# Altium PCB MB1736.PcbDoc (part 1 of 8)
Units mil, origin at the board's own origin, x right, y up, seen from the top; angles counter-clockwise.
Board outline 5905.51 x 3779.53 mil, 6 copper layers (Top Layer, L2_GND, L3_SIG, L4_VCC, L5_GND, Bottom Layer), stack 117.811 mil thick; 481 components, 387 nets, 1904 pads, 1200 vias.
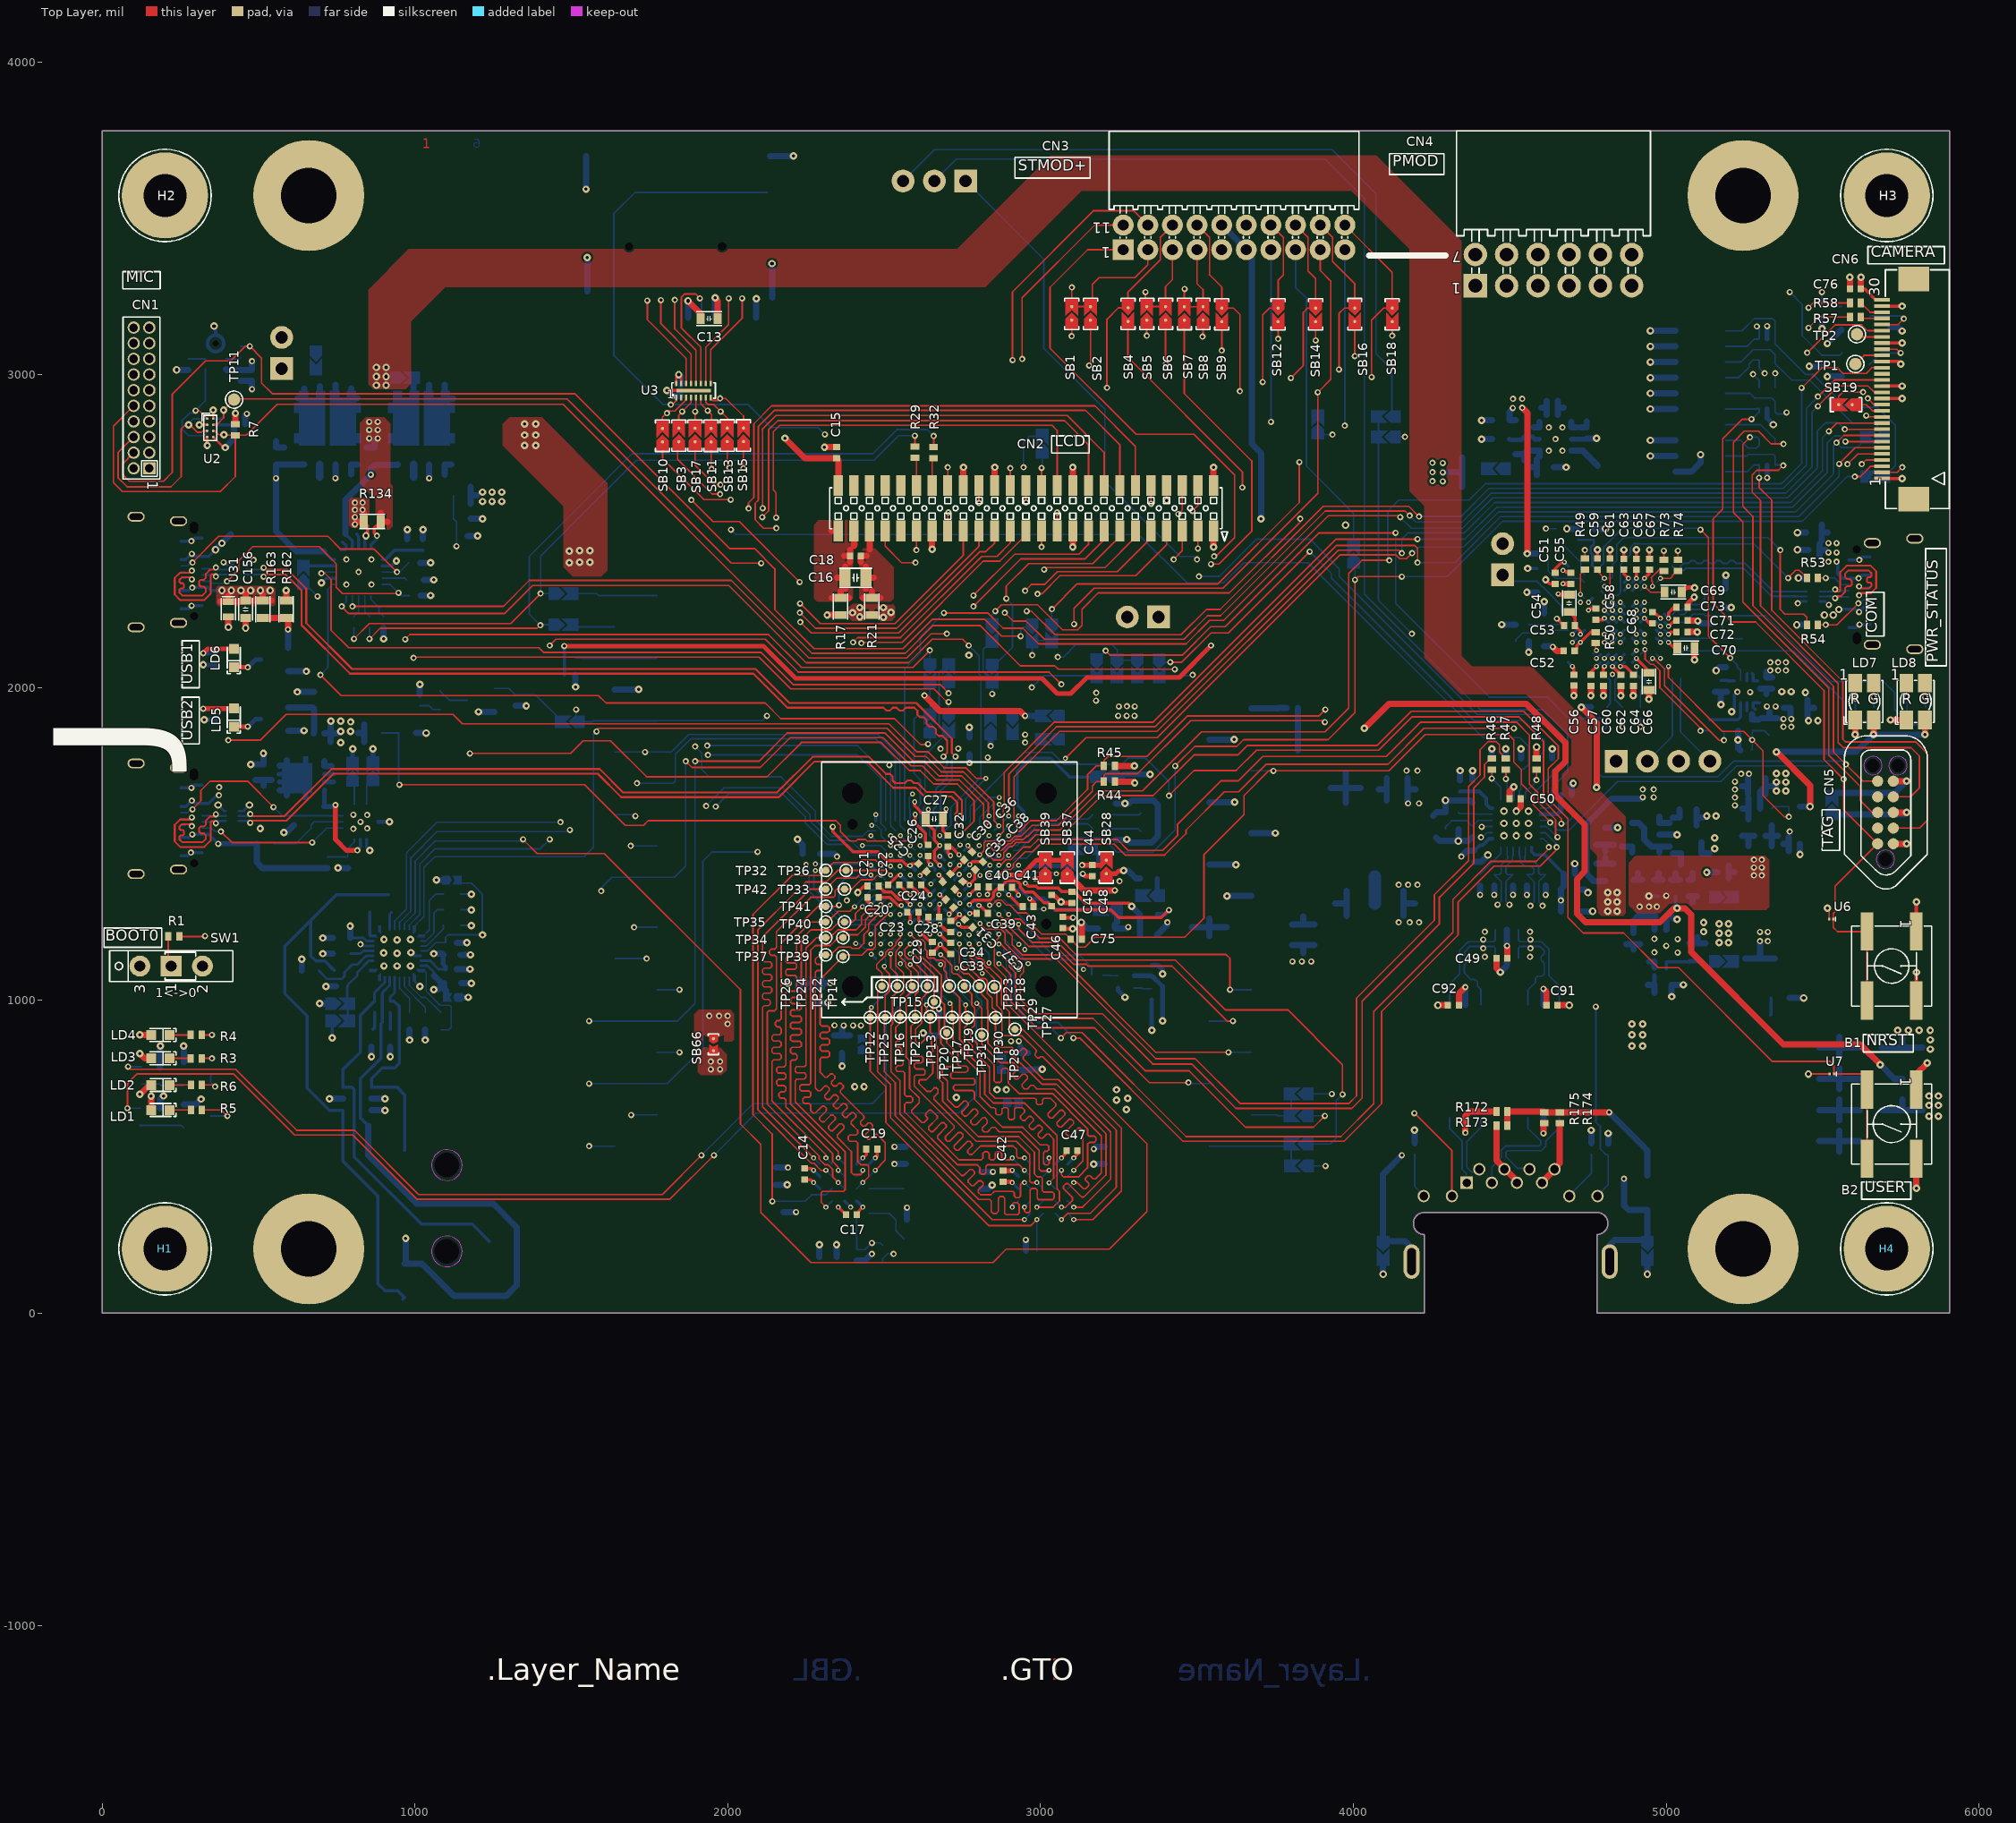
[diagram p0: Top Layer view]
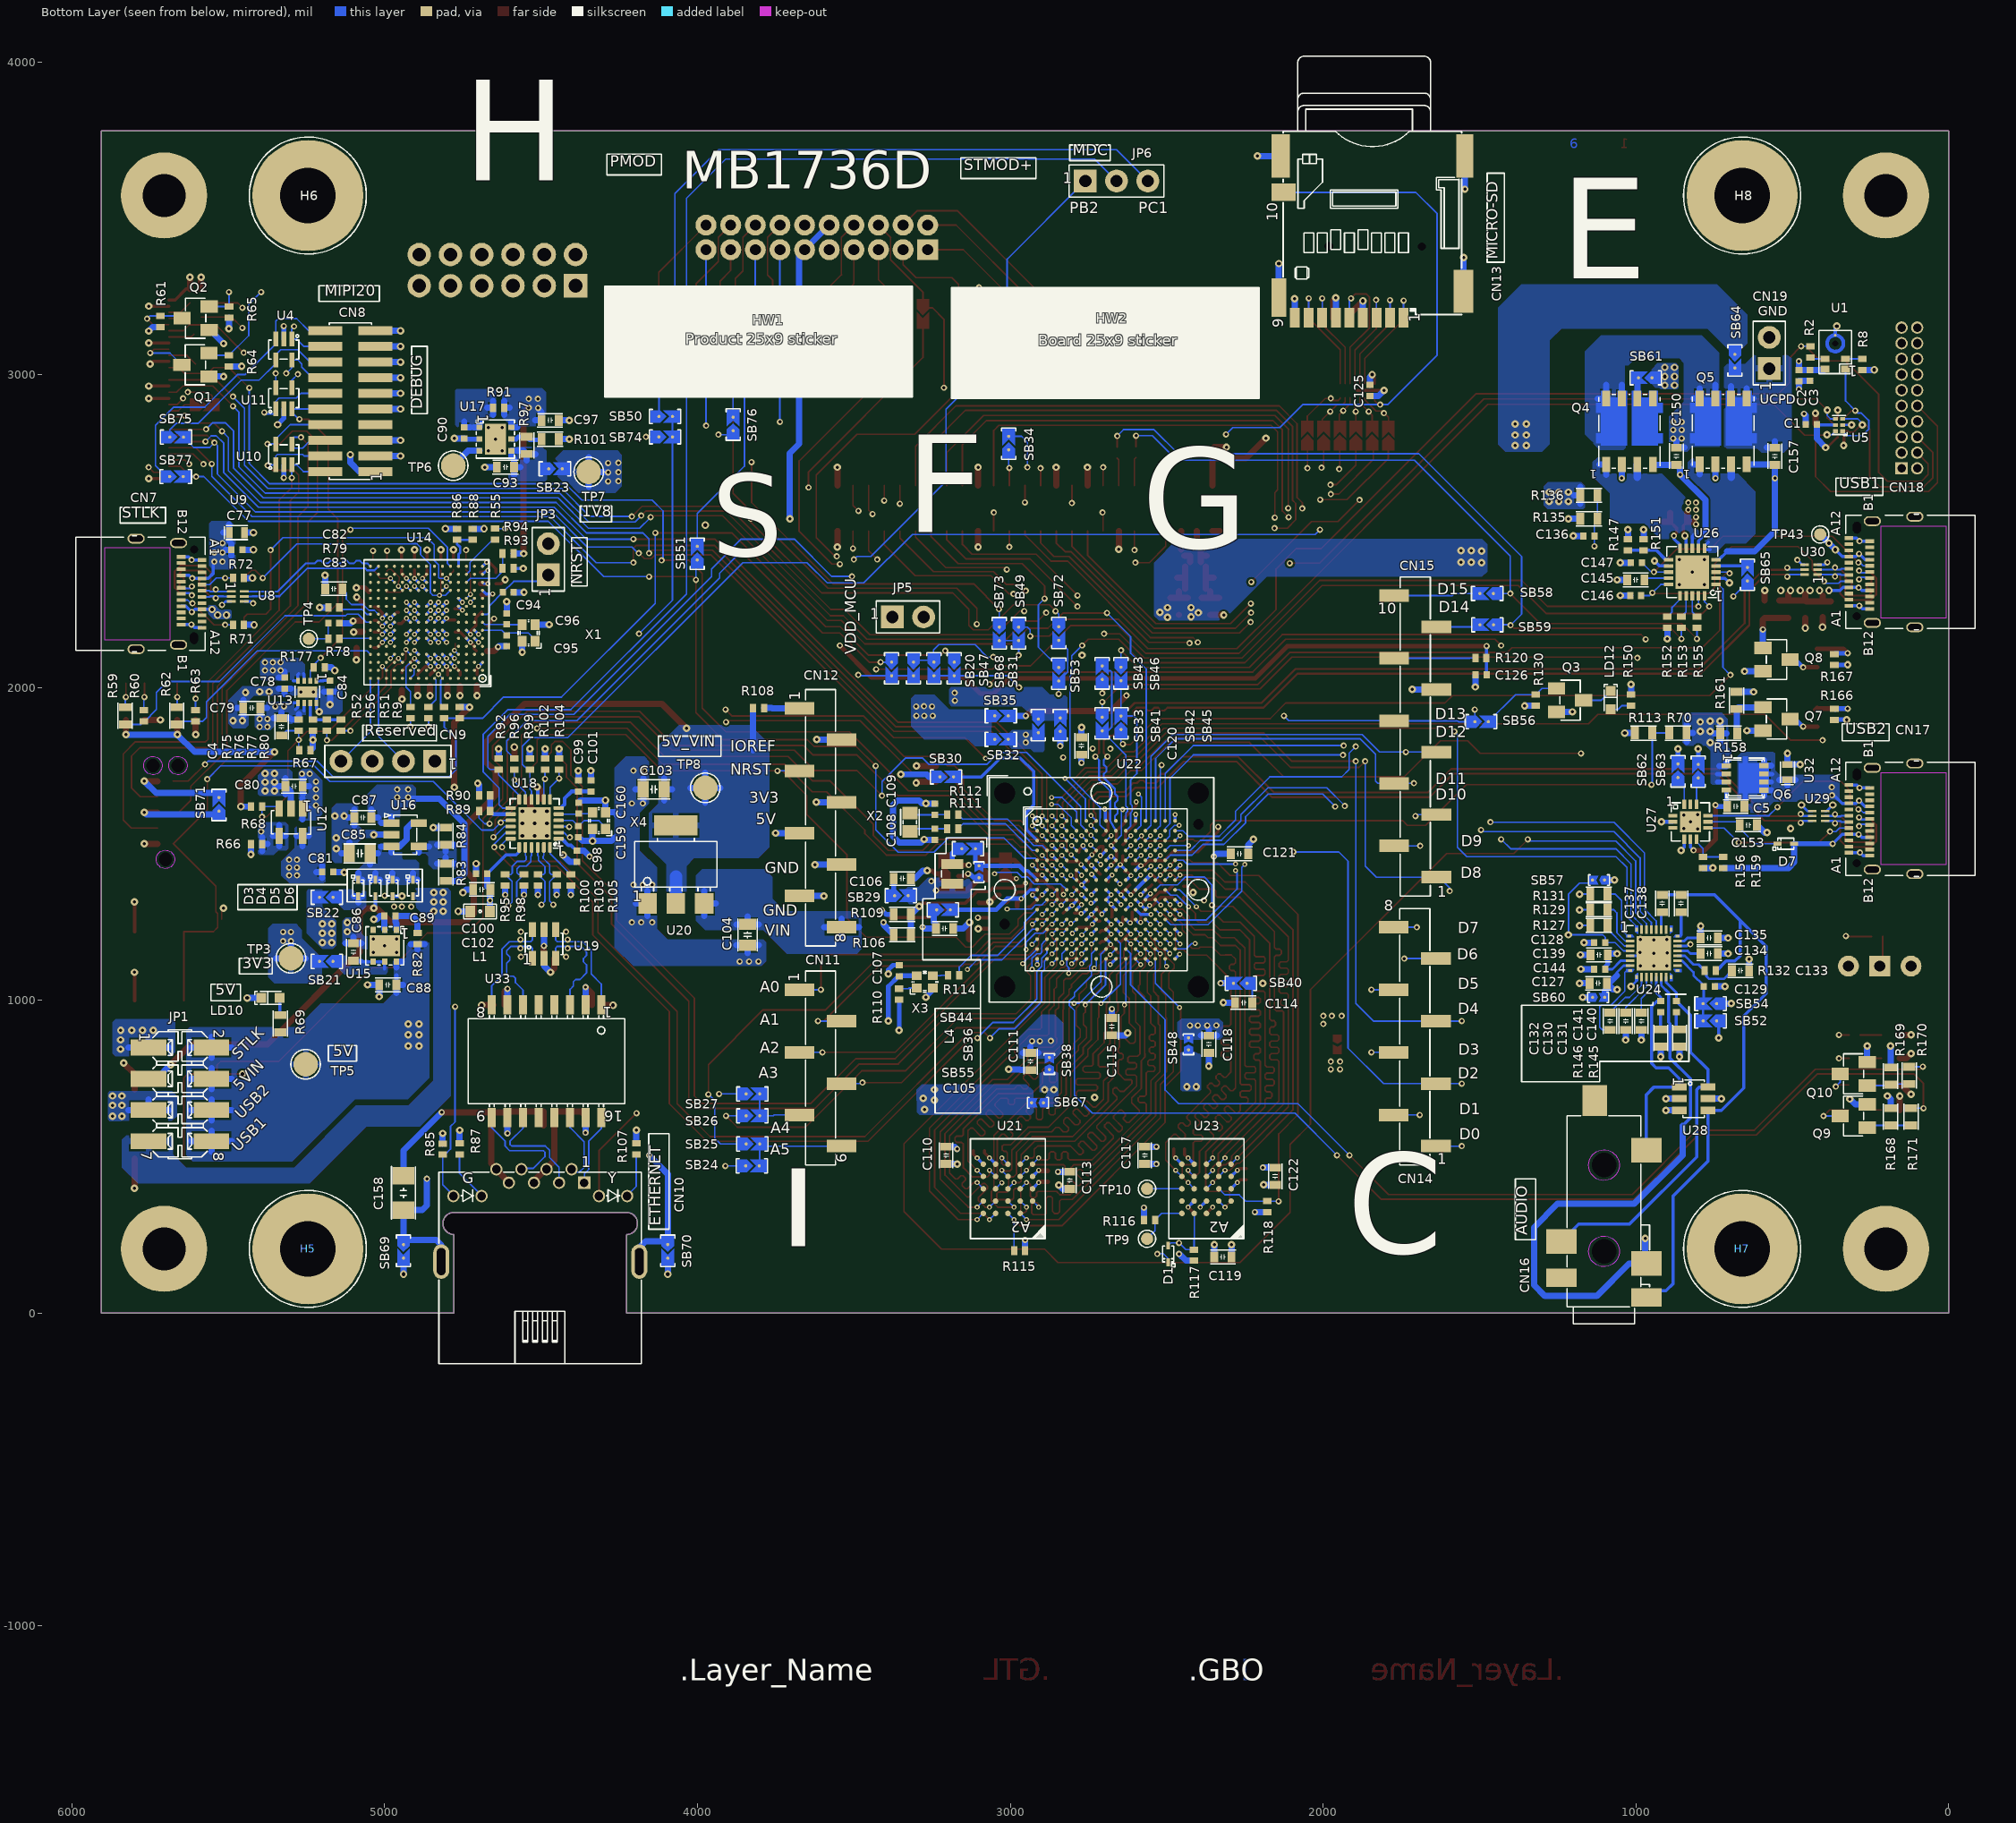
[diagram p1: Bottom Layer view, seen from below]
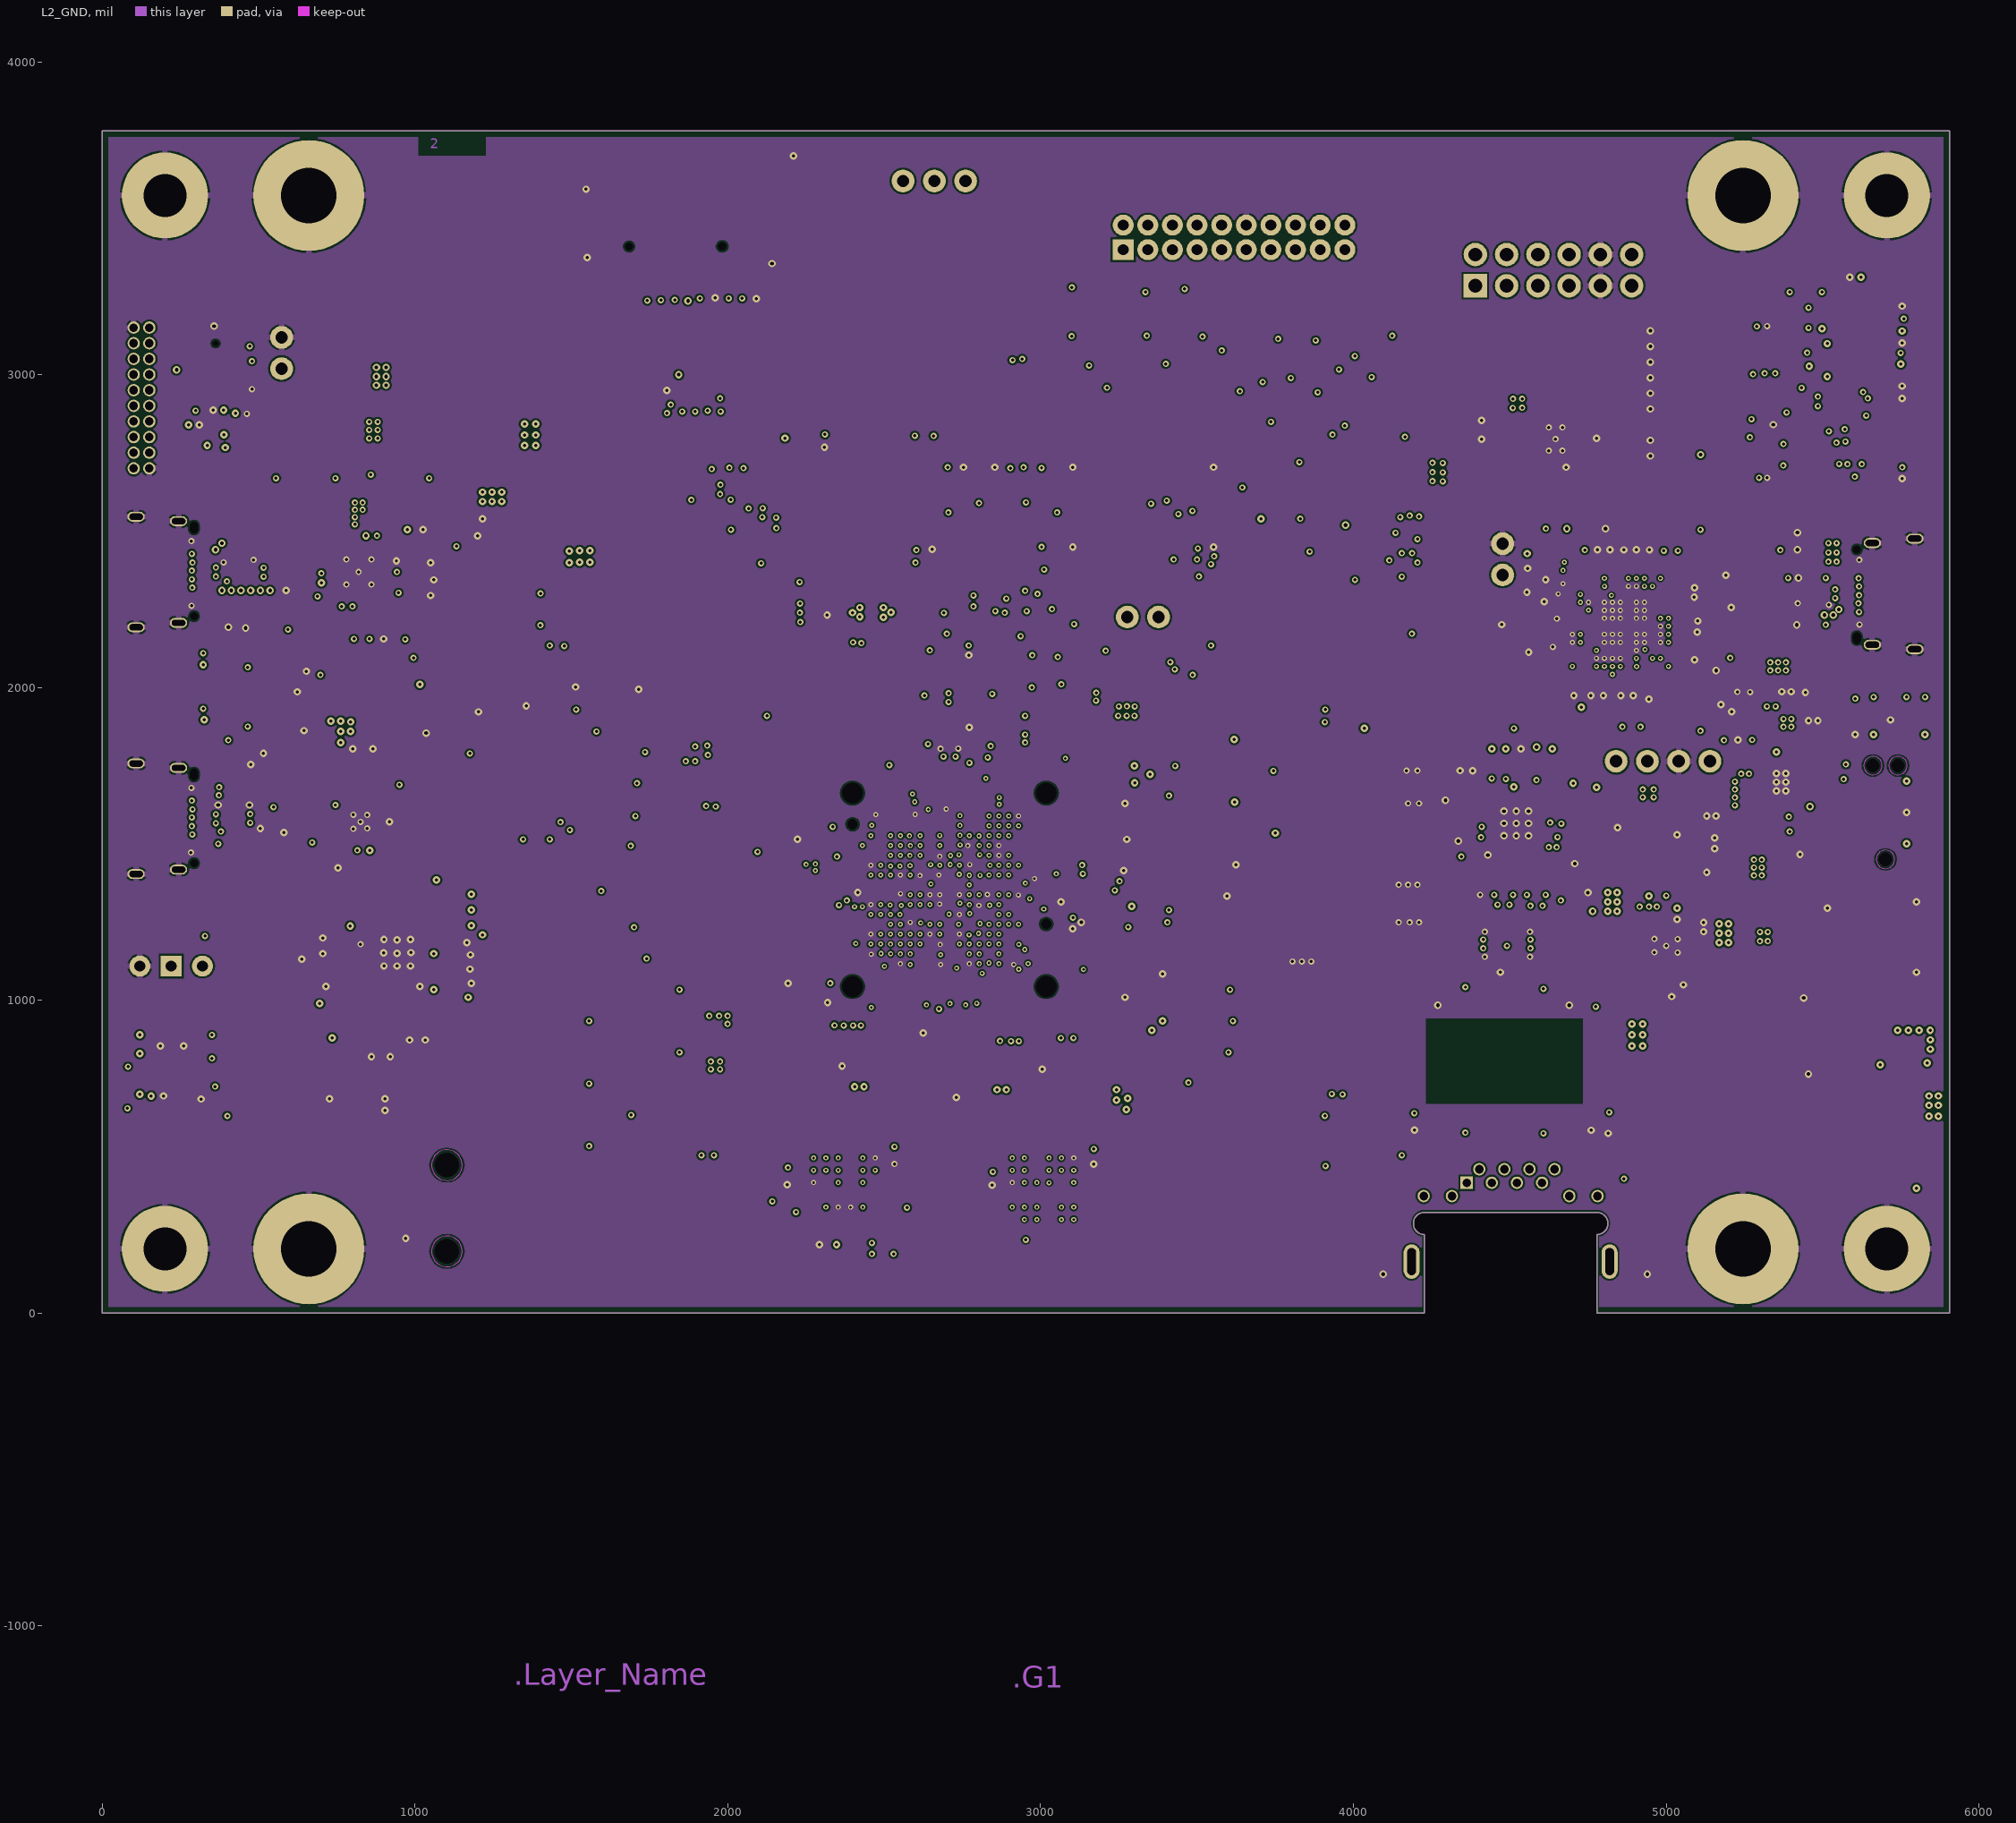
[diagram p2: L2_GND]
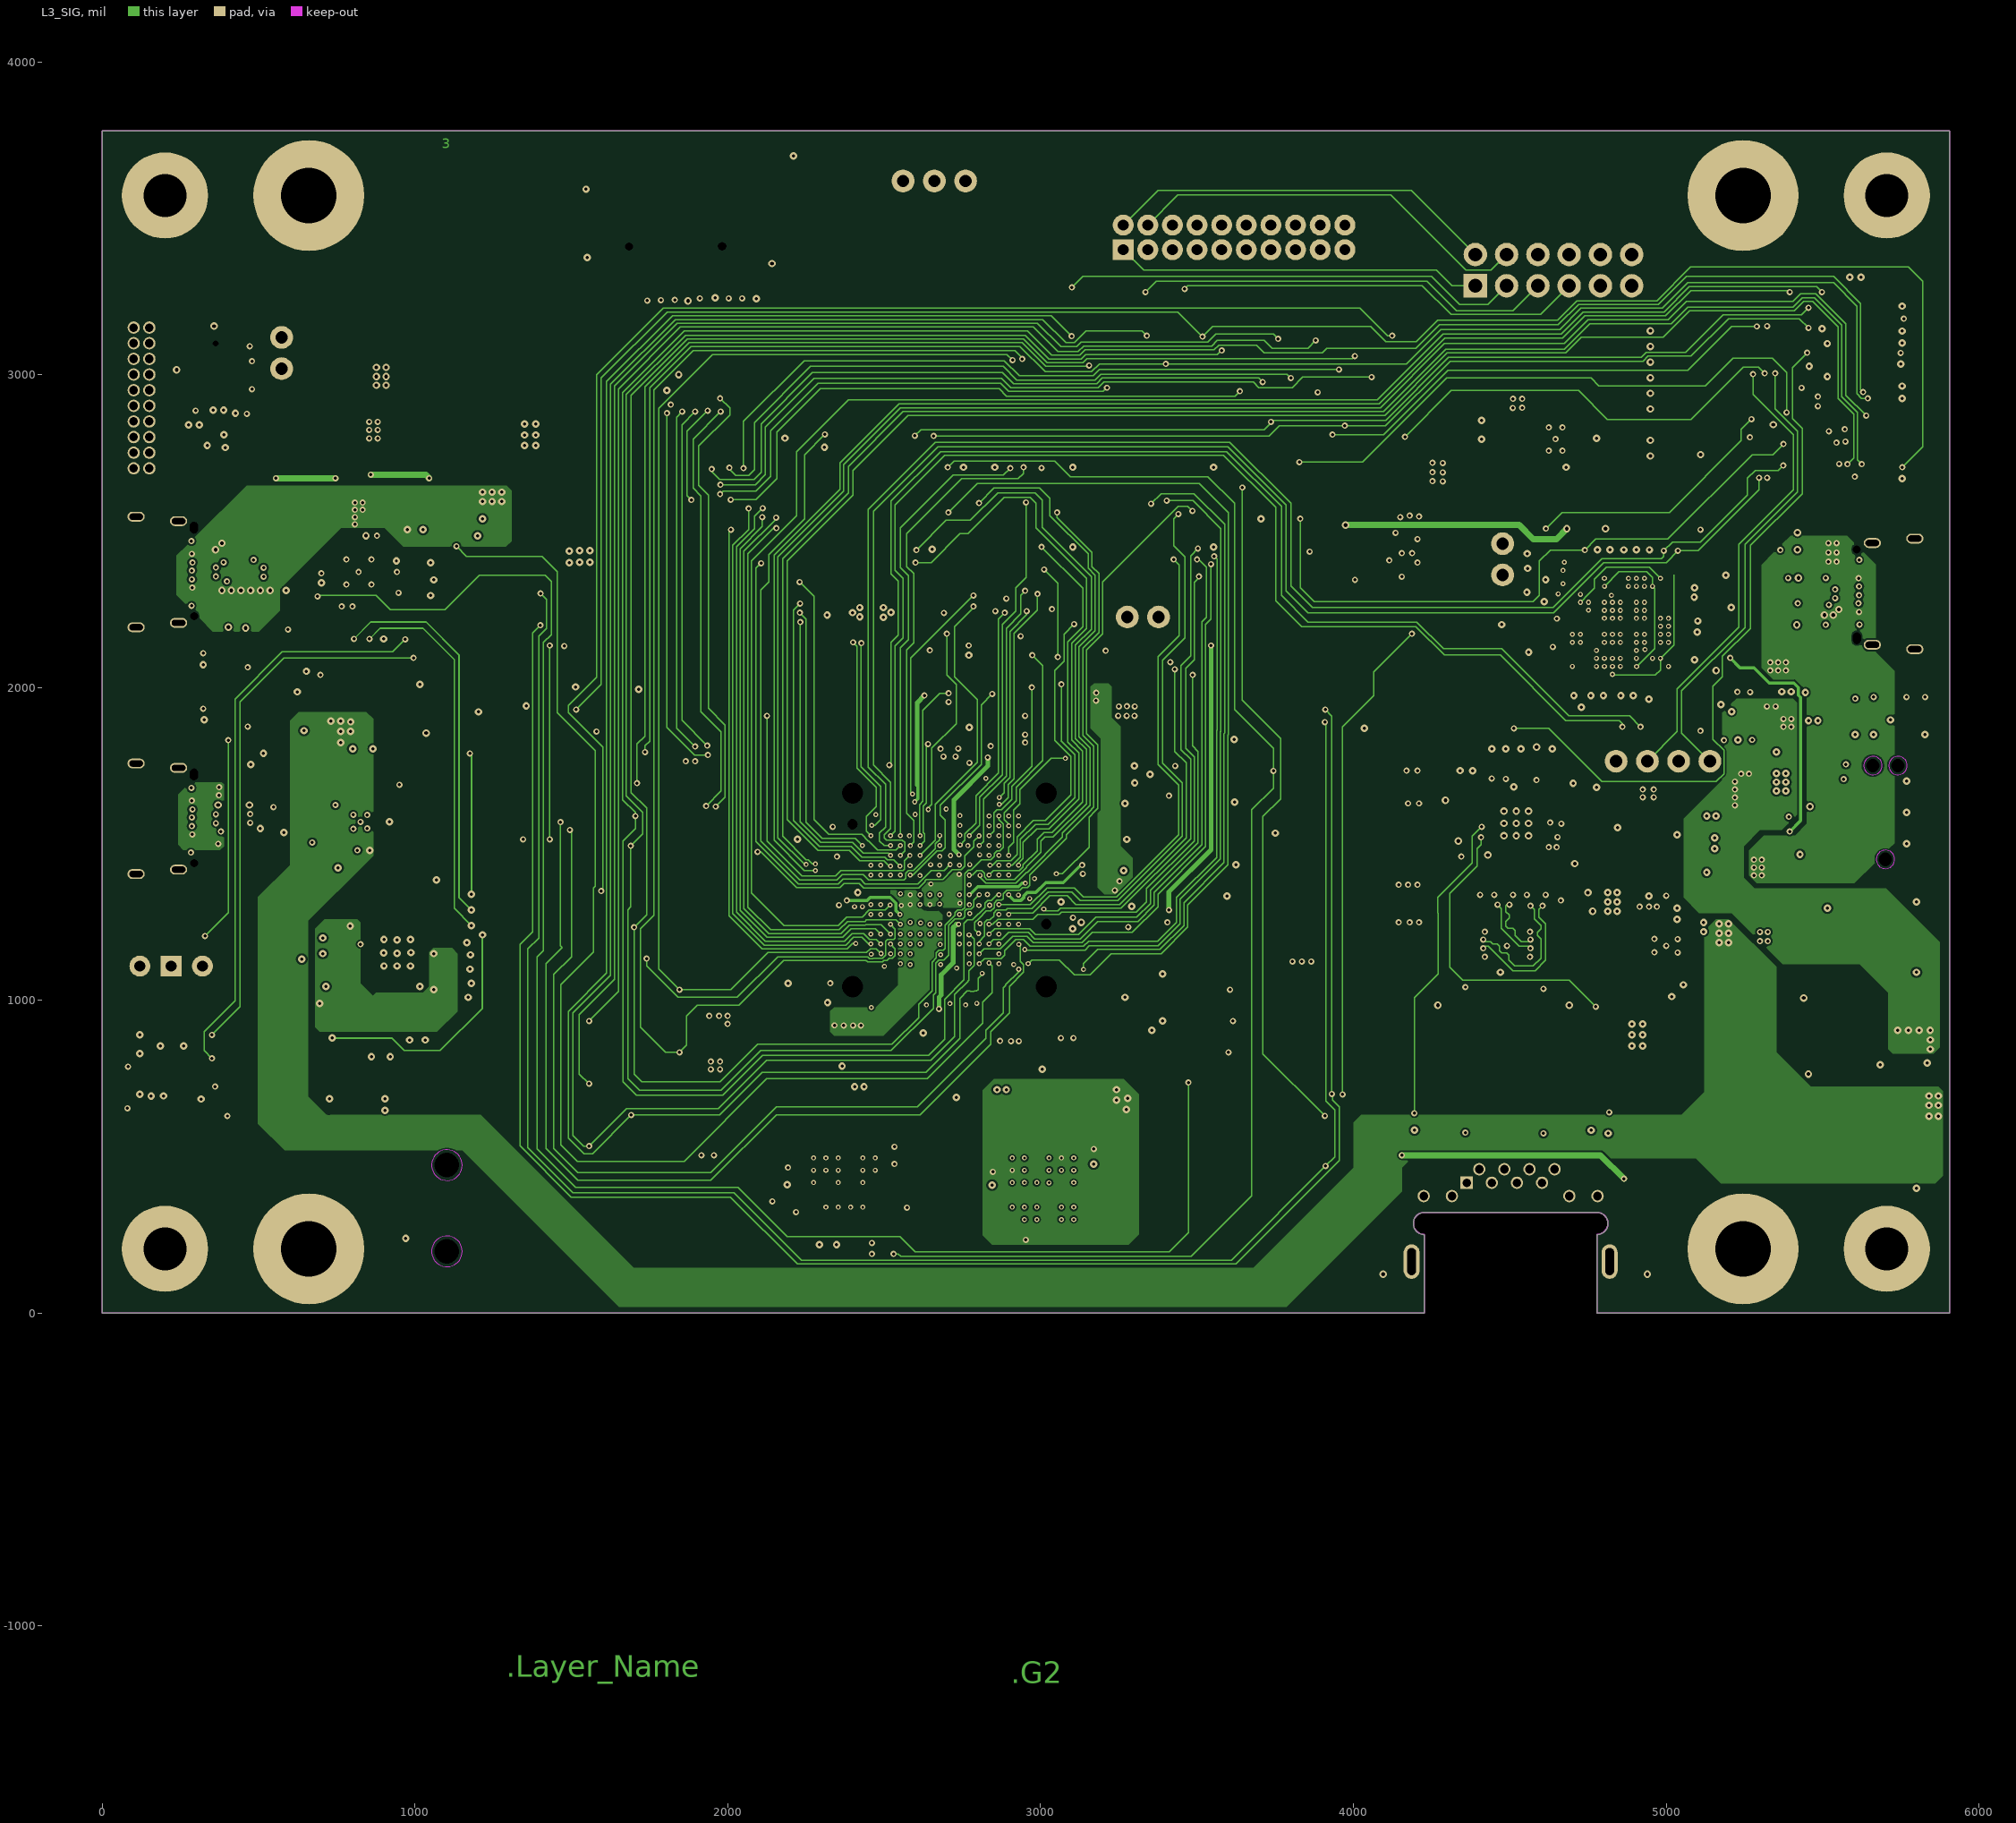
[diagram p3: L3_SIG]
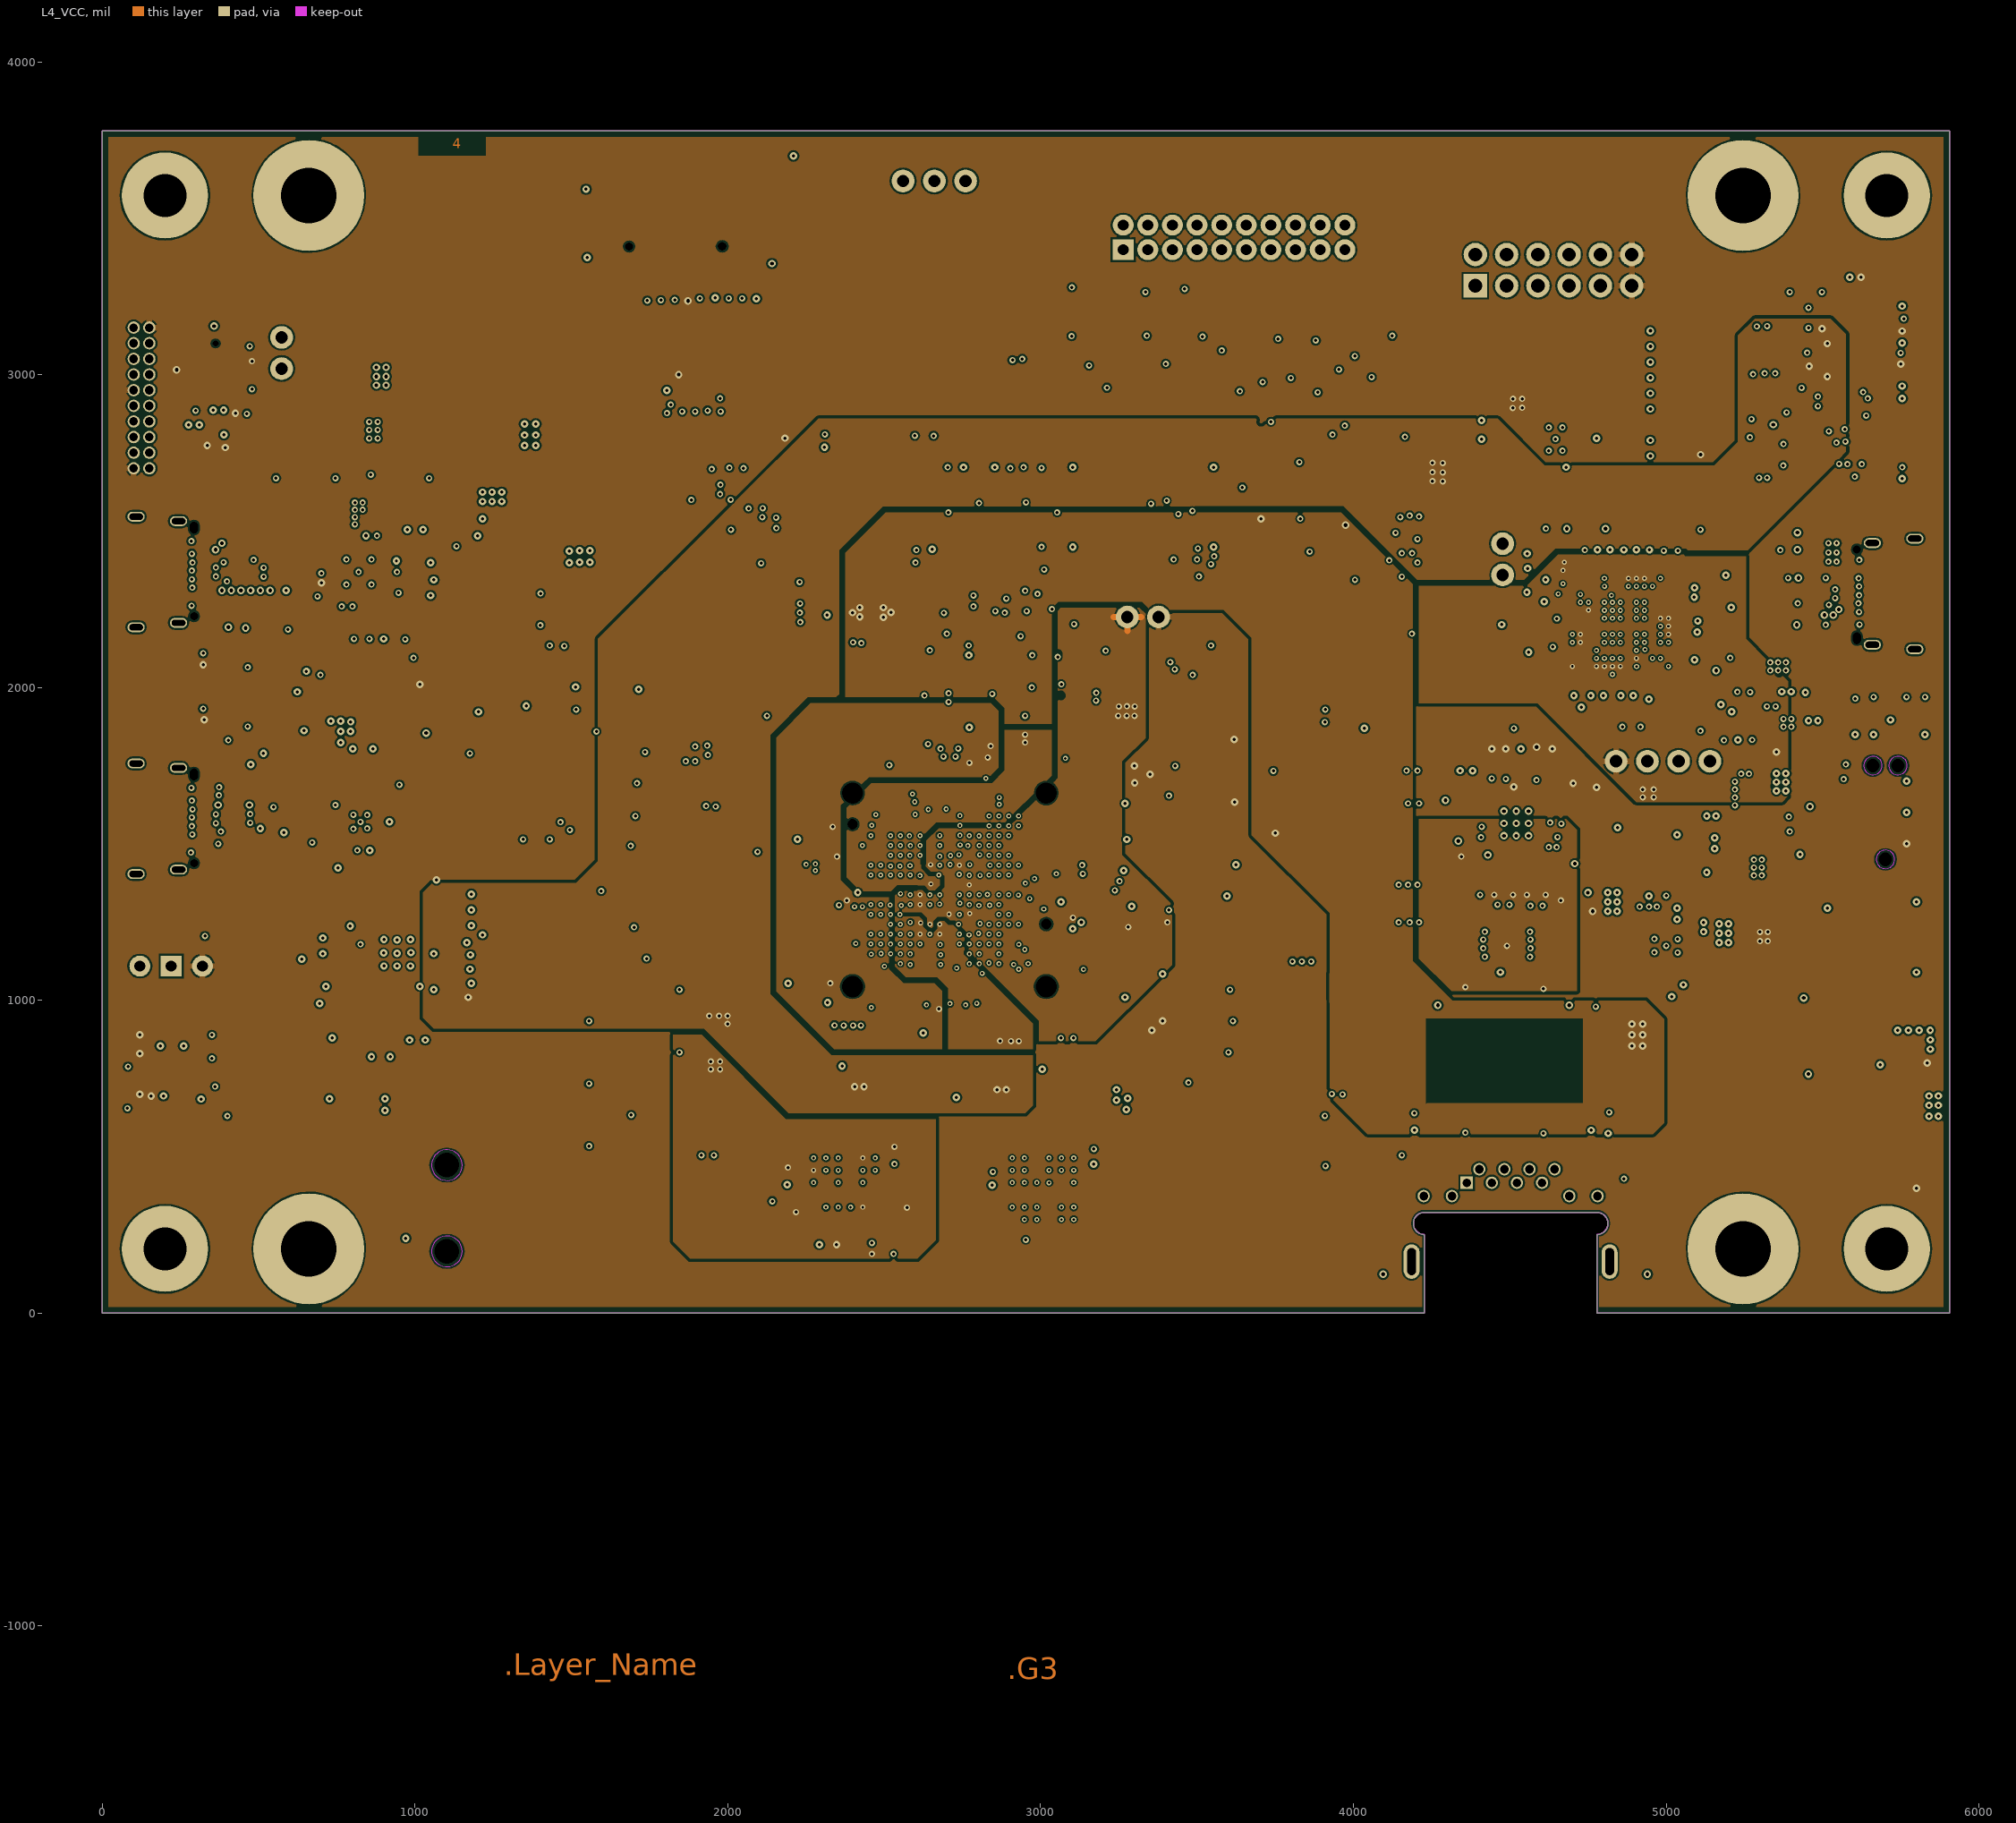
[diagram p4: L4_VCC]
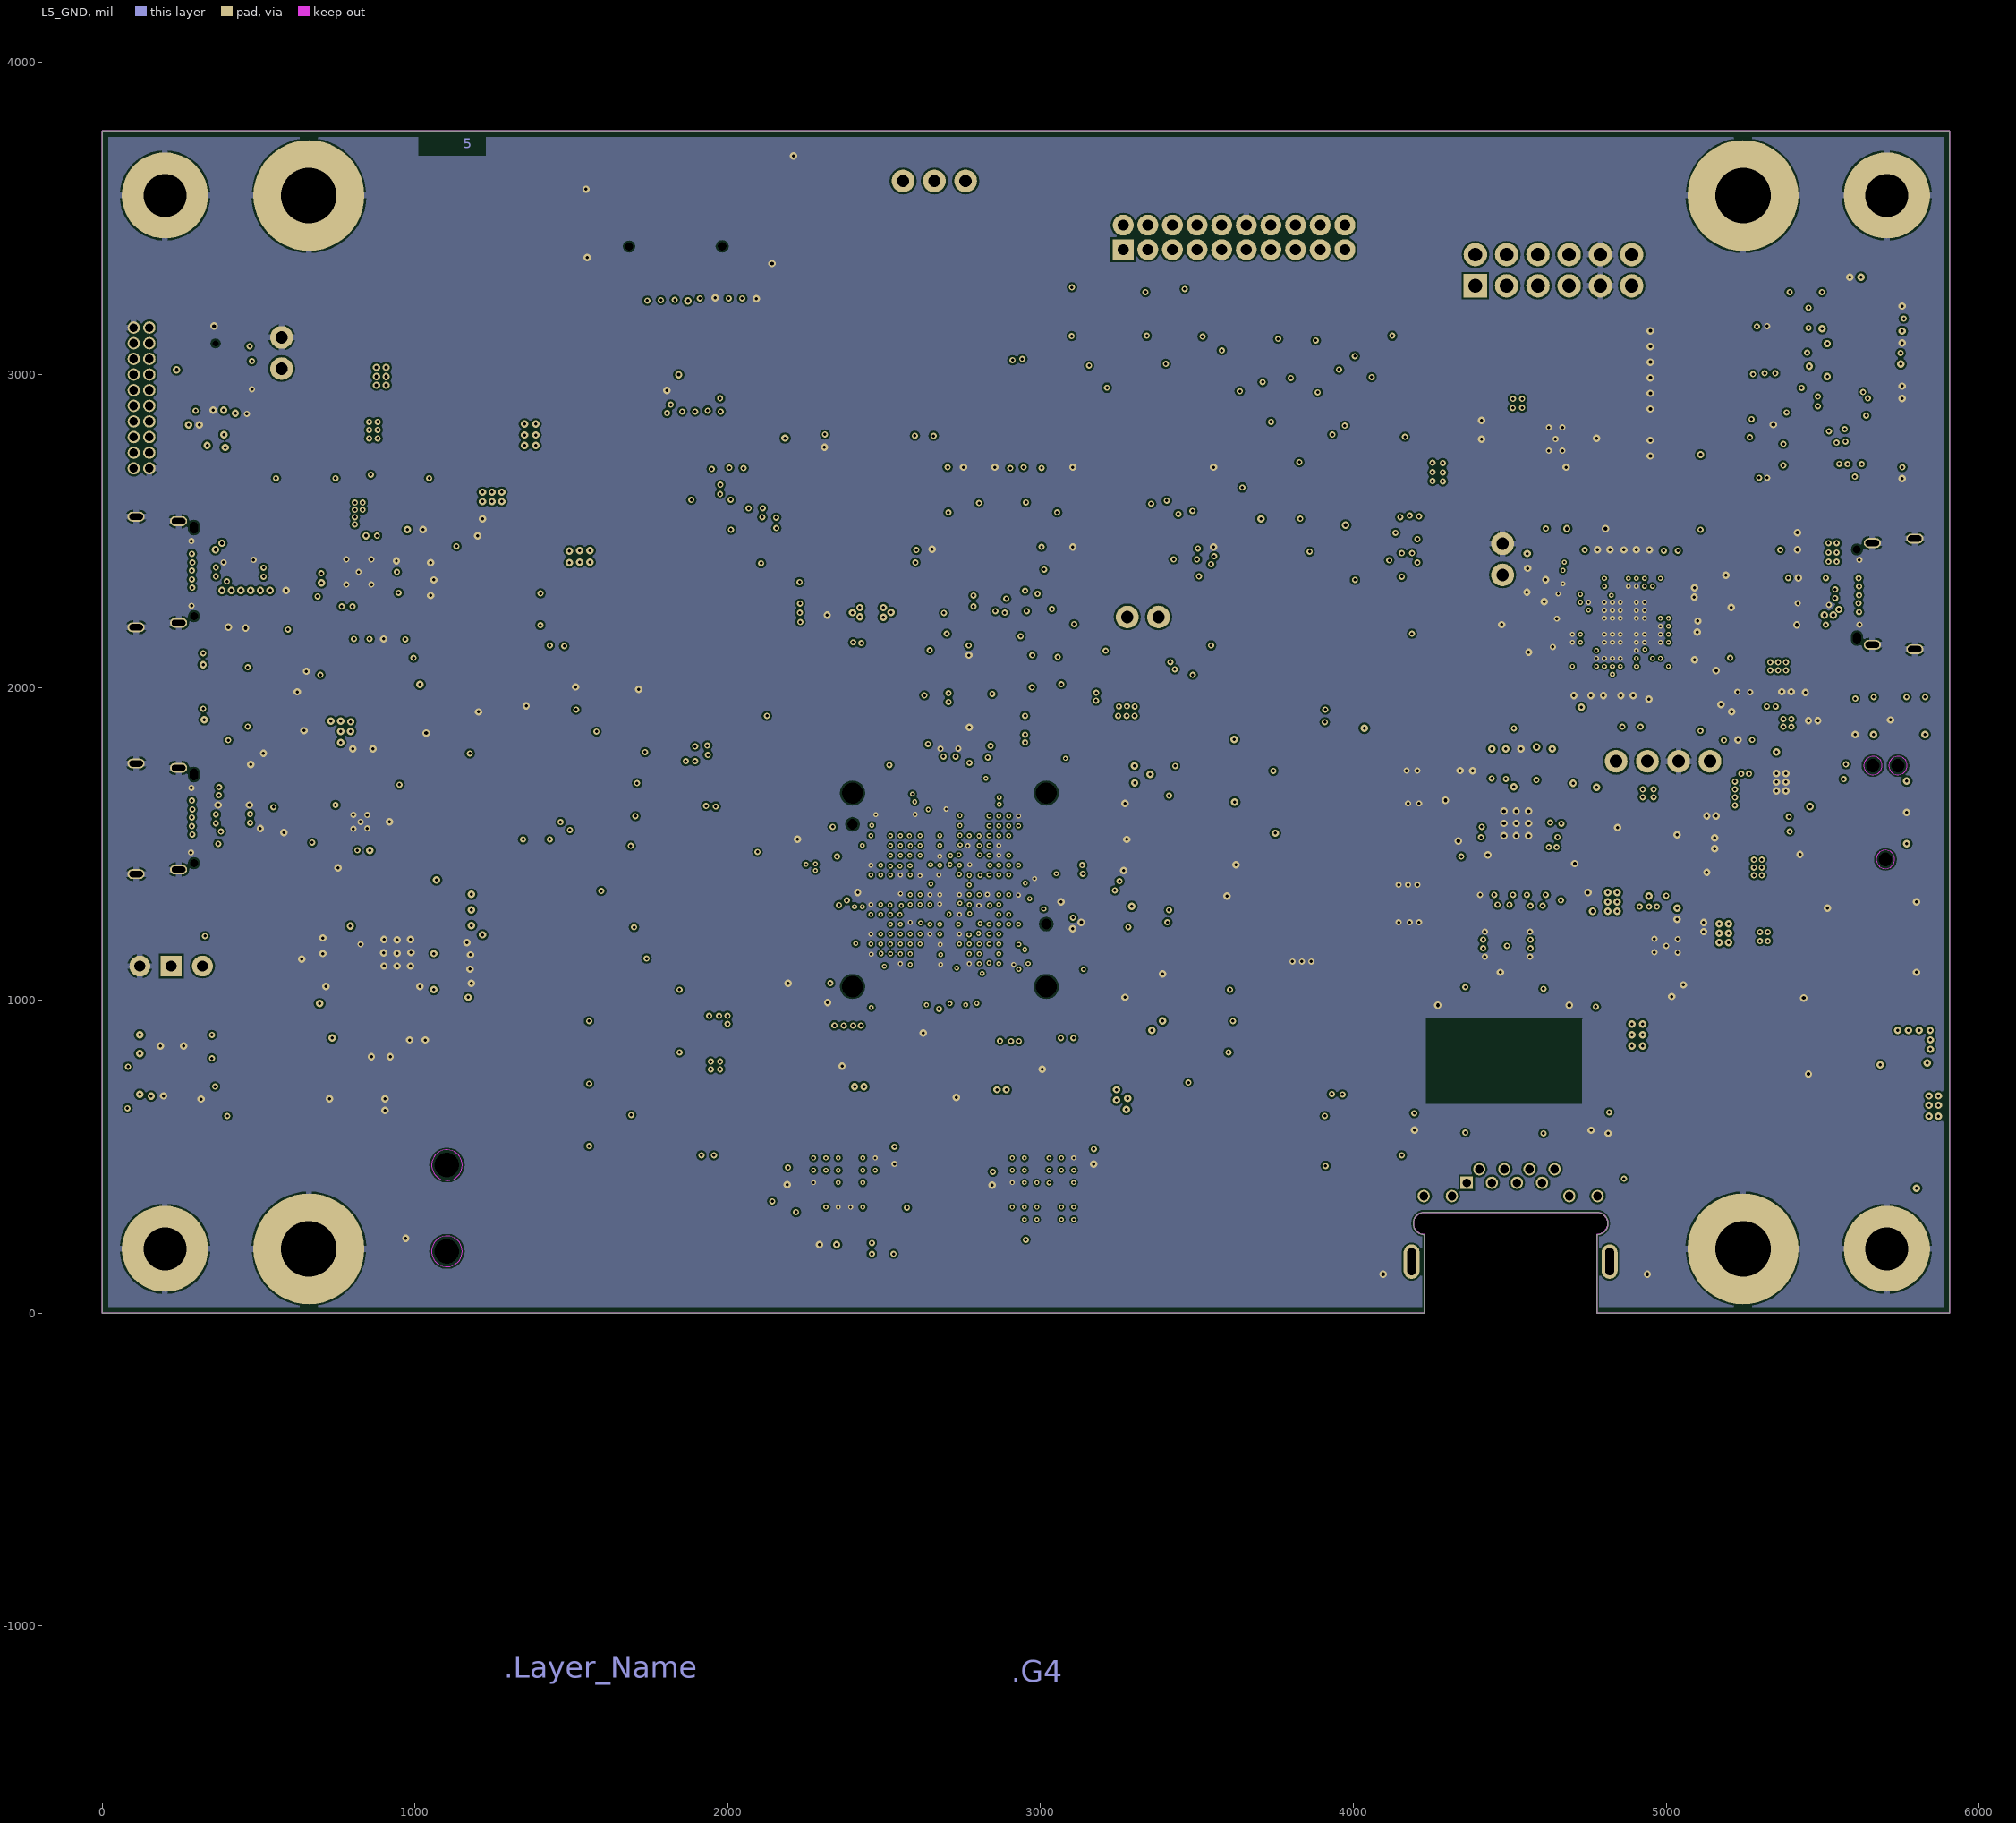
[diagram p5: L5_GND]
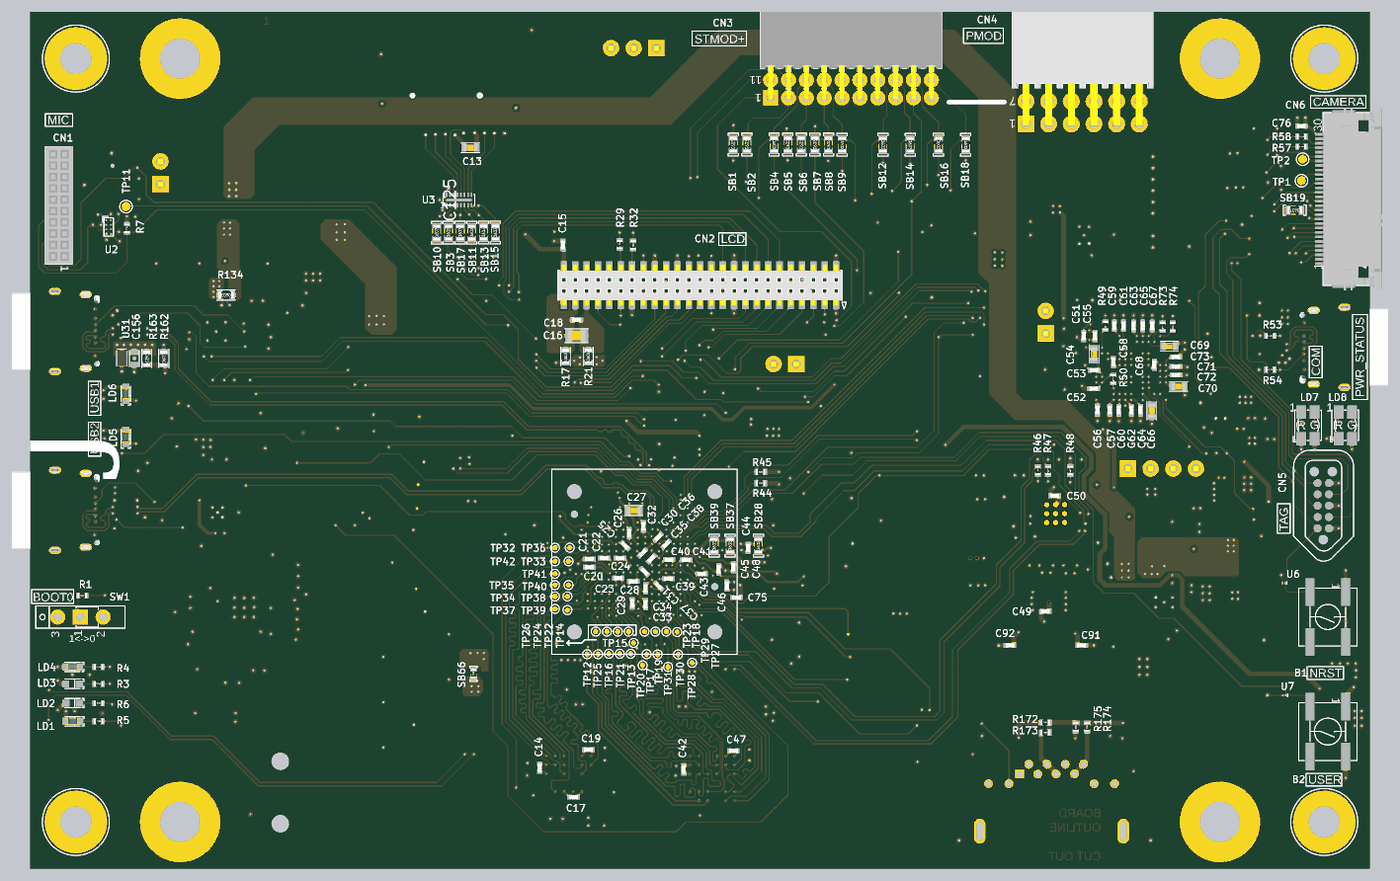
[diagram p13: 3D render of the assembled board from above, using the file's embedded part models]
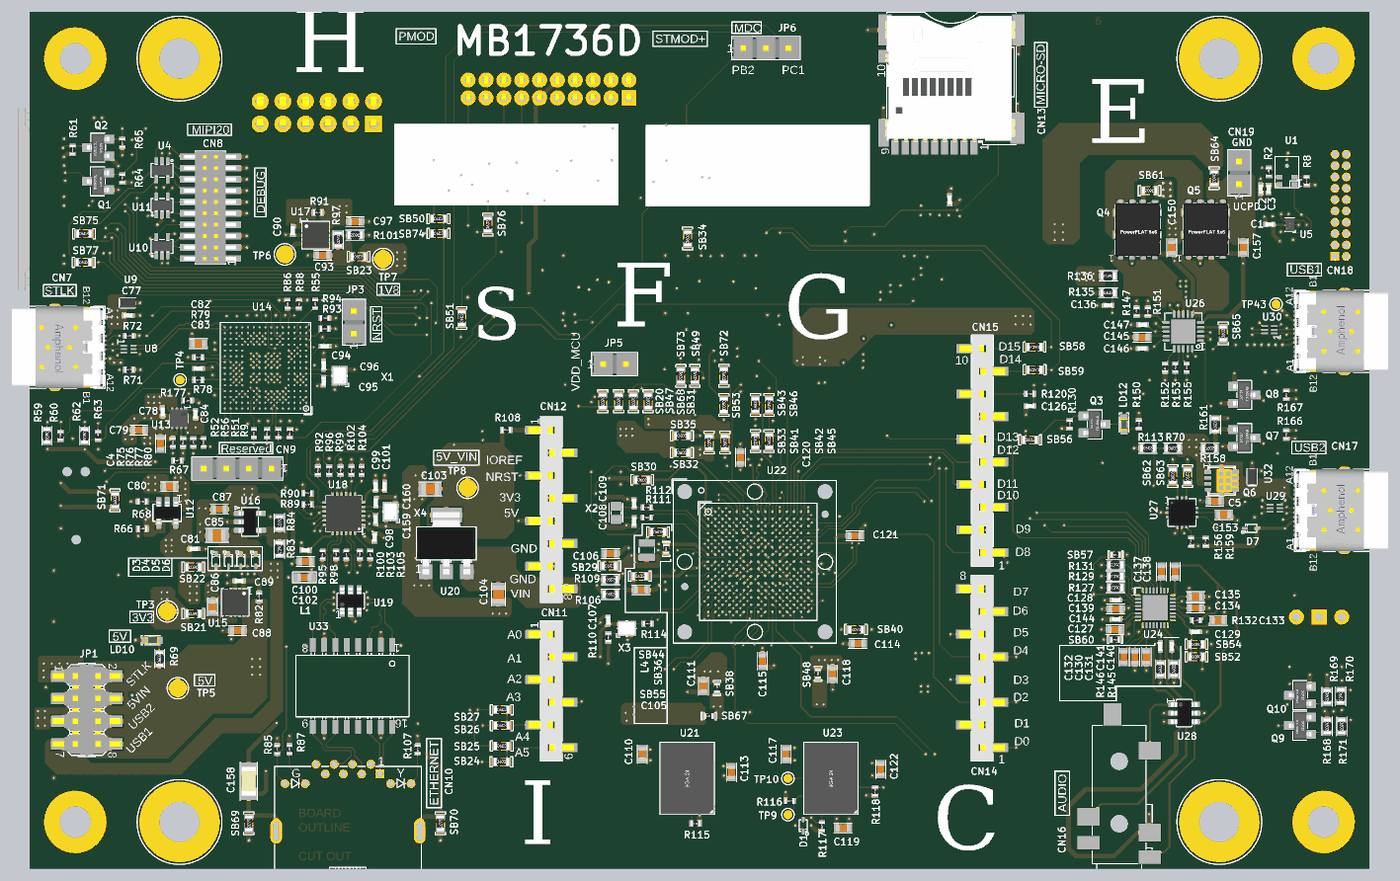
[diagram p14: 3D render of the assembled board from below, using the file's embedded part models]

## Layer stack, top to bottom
Top Solder: solder mask 0.591, Solder Resist, Dk 3.5
Top Layer: signal copper 1.378
Dielectric 1: dielectric 59.055, FR-4, Dk 4.8
L2_GND: signal copper 1.4
Dielectric3: dielectric 12.6, FR-4, Dk 4.8
L3_SIG: signal copper 1.4
Dielectric2: dielectric 12.6, FR-4, Dk 4.8
L4_VCC: signal copper 1.4
Dielectric5: dielectric 12.6, FR-4, Dk 4.8
L5_GND: signal copper 1.4
Dielectric4: dielectric 12.6, FR-4, Dk 4.8
Bottom Layer: signal copper 1.378
Bottom Solder: solder mask 0.591, Solder Resist, Dk 3.5

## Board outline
0,0 0,3779.53 5905.51,3779.53 5905.51,0 4778.35,0 4778.35,251.42 ccw(c4778.38,286.85) 4778.35,322.28 4227.16,322.28 ccw(c4227.13,286.85) 4227.16,251.42 4227.16,0

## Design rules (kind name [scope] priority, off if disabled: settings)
Clearance Clearance_SB [HasFootprint('SOLDER-BRIDGE_R0402-0R','SOLDER-BRIDGE_R0603-0R')] p1: gap=6 ignorepadtopadclearanceinfootprint=FALSE
Clearance Clearance_U1 [WithinRoom('Room_U1','Room_U22','Room_U21','Room_U23','Room_U14','Room_U24')] p2: gap=4 ignorepadtopadclearanceinfootprint=FALSE except(5: Via-Fill Via-Poly Via-Region; 6: Arc-Fill Arc-Poly Arc-Region Track-Fill Track-Poly Track-Region SMDPad-Fill SMDPad-Poly SMDPad-Region THPad-Fill THPad-Poly THPad-Region; 10: Fill-Fill Fill-Poly Fill-Region Poly-Poly Poly-Region Region-Region)
Clearance Clearance_CN13 [All] p3: gap=5 ignorepadtopadclearanceinfootprint=FALSE except(3.9: Arc-THPad Track-THPad; 6: Arc-Fill Arc-Poly Arc-Region Track-Fill Track-Poly Track-Region SMDPad-Fill SMDPad-Poly SMDPad-Region THPad-Fill THPad-Poly THPad-Region Via-Fill Via-Poly Via-Region; 8: Arc-Arc Arc-Track Track-Track; 10: Fill-Fill Fill-Poly Fill-Region Poly-Poly Poly-Region Region-Region)
Clearance [All] p4: gap=5 ignorepadtopadclearanceinfootprint=FALSE except(6: Arc-Fill Arc-Poly Arc-Region Track-Fill Track-Poly Track-Region SMDPad-Fill SMDPad-Poly SMDPad-Region THPad-Fill THPad-Poly THPad-Region Via-Fill Via-Poly Via-Region; 8: Arc-Arc Arc-Track Track-Track; 20: Fill-Fill Fill-Poly Fill-Region Poly-Poly Poly-Region Region-Region)
ComponentClearance [All] p1: gap=7.87 collisioncheckmode=3 verticalgap=7.87 showdistances=FALSE
DiffPairsRouting DiffPairsRouting_90OHM [All] p1: maxlimit=10 minlimit=4 mostfreqgap=8.9 toplayer_minwidth=4 toplayer_maxwidth=8.9 toplayer_prefwidth=6.1 midlayer1_minwidth=4 midlayer1_maxwidth=8.9 midlayer1_prefwidth=6.1 midlayer2_minwidth=4 midlayer2_maxwidth=9.9 midlayer2_prefwidth=5.1 midlayer3_minwidth=4 midlayer3_maxwidth=8.9 midlayer3_prefwidth=6.1 midlayer4_minwidth=4 midlayer4_maxwidth=8.9 midlayer4_prefwidth=6.1 bottomlayer_minwidth=4 bottomlayer_maxwidth=8.9 bottomlayer_prefwidth=6.1 substack1={5D5844C5-C1B0-405F-A42B-4ABDA7DE1448} toplayer_{5d5844c5-c1b0-405f-a42b-4abda7de1448}_minwidth=15 toplayer_{5d5844c5-c1b0-405f-a42b-4abda7de1448}_maxwidth=15 toplayer_{5d5844c5-c1b0-405f-a42b-4abda7de1448}_prefwidth=15 midlayer1_{5d5844c5-c1b0-405f-a42b-4abda7de1448}_minwidth=15 midlayer1_{5d5844c5-c1b0-405f-a42b-4abda7de1448}_maxwidth=15 midlayer1_{5d5844c5-c1b0-405f-a42b-4abda7de1448}_prefwidth=15 midlayer2_{5d5844c5-c1b0-405f-a42b-4abda7de1448}_minwidth=15 midlayer2_{5d5844c5-c1b0-405f-a42b-4abda7de1448}_maxwidth=15 midlayer2_{5d5844c5-c1b0-405f-a42b-4abda7de1448}_prefwidth=15 midlayer3_{5d5844c5-c1b0-405f-a42b-4abda7de1448}_minwidth=15 midlayer3_{5d5844c5-c1b0-405f-a42b-4abda7de1448}_maxwidth=15 midlayer3_{5d5844c5-c1b0-405f-a42b-4abda7de1448}_prefwidth=15 midlayer4_{5d5844c5-c1b0-405f-a42b-4abda7de1448}_minwidth=15 midlayer4_{5d5844c5-c1b0-405f-a42b-4abda7de1448}_maxwidth=15 midlayer4_{5d5844c5-c1b0-405f-a42b-4abda7de1448}_prefwidth=15 bottomlayer_{5d5844c5-c1b0-405f-a42b-4abda7de1448}_minwidth=15 bottomlayer_{5d5844c5-c1b0-405f-a42b-4abda7de1448}_maxwidth=15 bottomlayer_{5d5844c5-c1b0-405f-a42b-4abda7de1448}_prefwidth=15 maxuncoupledlength=500
DiffPairsRouting DiffPairsRouting_100OHM [All] p2: maxlimit=10.9 minlimit=4 mostfreqgap=10.9 toplayer_maxgap=10 toplayer_prefgap=9.9 toplayer_minwidth=4 toplayer_maxwidth=5.1 toplayer_prefwidth=5.1 midlayer1_maxgap=10 midlayer1_prefgap=9.9 midlayer1_minwidth=4 midlayer1_maxwidth=5.1 midlayer1_prefwidth=5.1 midlayer2_minwidth=4 midlayer2_maxwidth=5.1 midlayer2_prefwidth=4.1 midlayer3_maxgap=10 midlayer3_prefgap=9.9 midlayer3_minwidth=4 midlayer3_maxwidth=5.1 midlayer3_prefwidth=5.1 midlayer4_maxgap=10 midlayer4_prefgap=9.9 midlayer4_minwidth=4 midlayer4_maxwidth=5.1 midlayer4_prefwidth=5.1 bottomlayer_maxgap=10 bottomlayer_prefgap=9.9 bottomlayer_minwidth=4 bottomlayer_maxwidth=5.1 bottomlayer_prefwidth=5.1 substack1={5D5844C5-C1B0-405F-A42B-4ABDA7DE1448} toplayer_{5d5844c5-c1b0-405f-a42b-4abda7de1448}_minwidth=15 toplayer_{5d5844c5-c1b0-405f-a42b-4abda7de1448}_maxwidth=15 toplayer_{5d5844c5-c1b0-405f-a42b-4abda7de1448}_prefwidth=15 midlayer1_{5d5844c5-c1b0-405f-a42b-4abda7de1448}_minwidth=15 midlayer1_{5d5844c5-c1b0-405f-a42b-4abda7de1448}_maxwidth=15 midlayer1_{5d5844c5-c1b0-405f-a42b-4abda7de1448}_prefwidth=15 midlayer2_{5d5844c5-c1b0-405f-a42b-4abda7de1448}_minwidth=15 midlayer2_{5d5844c5-c1b0-405f-a42b-4abda7de1448}_maxwidth=15 midlayer2_{5d5844c5-c1b0-405f-a42b-4abda7de1448}_prefwidth=15 midlayer3_{5d5844c5-c1b0-405f-a42b-4abda7de1448}_minwidth=15 midlayer3_{5d5844c5-c1b0-405f-a42b-4abda7de1448}_maxwidth=15 midlayer3_{5d5844c5-c1b0-405f-a42b-4abda7de1448}_prefwidth=15 midlayer4_{5d5844c5-c1b0-405f-a42b-4abda7de1448}_minwidth=15 midlayer4_{5d5844c5-c1b0-405f-a42b-4abda7de1448}_maxwidth=15 midlayer4_{5d5844c5-c1b0-405f-a42b-4abda7de1448}_prefwidth=15 bottomlayer_{5d5844c5-c1b0-405f-a42b-4abda7de1448}_minwidth=15 bottomlayer_{5d5844c5-c1b0-405f-a42b-4abda7de1448}_maxwidth=15 bottomlayer_{5d5844c5-c1b0-405f-a42b-4abda7de1448}_prefwidth=15 maxuncoupledlength=500
HoleSize [All] p1: absolutevalues=TRUE maxlimit=500 minlimit=1 maxpercent=80.000 minpercent=20.000
HoleToHoleClearance [All] p1: gap=9.5 allowstackedmicrovias=TRUE
MatchedLengths "Schematic Matched Net Lengths_32" [InNet('HEXASPI_NCS')] p1: tolerance=1000 checknetsindiffpair=FALSE checkdiffpairvsdiffpair=TRUE checkxsignals=TRUE checkothers=TRUE
MatchedLengths "Schematic Matched Net Lengths_31" [InNet('OCTOSPI_NCS')] p2: tolerance=1000 checknetsindiffpair=FALSE checkdiffpairvsdiffpair=TRUE checkxsignals=TRUE checkothers=TRUE
MatchedLengths "Schematic Matched Net Lengths_30" [InNet('HEXASPI_IO4')] p3: tolerance=20 checknetsindiffpair=FALSE checkdiffpairvsdiffpair=TRUE checkxsignals=TRUE checkothers=TRUE
MatchedLengths "Schematic Matched Net Lengths_29" [InNet('HEXASPI_IO8')] p4: tolerance=20 checknetsindiffpair=FALSE checkdiffpairvsdiffpair=TRUE checkxsignals=TRUE checkothers=TRUE
MatchedLengths "Schematic Matched Net Lengths_28" [InNet('HEXASPI_IO5')] p5: tolerance=20 checknetsindiffpair=FALSE checkdiffpairvsdiffpair=TRUE checkxsignals=TRUE checkothers=TRUE
MatchedLengths "Schematic Matched Net Lengths_27" [InNet('OCTOSPI_IO5')] p6: tolerance=20 checknetsindiffpair=FALSE checkdiffpairvsdiffpair=TRUE checkxsignals=TRUE checkothers=TRUE
MatchedLengths "Schematic Matched Net Lengths_26" [InNet('OCTOSPI_IO6')] p7: tolerance=20 checknetsindiffpair=FALSE checkdiffpairvsdiffpair=TRUE checkxsignals=TRUE checkothers=TRUE
MatchedLengths "Schematic Matched Net Lengths_25" [InNet('HEXASPI_DQS1')] p8: tolerance=20 checknetsindiffpair=FALSE checkdiffpairvsdiffpair=TRUE checkxsignals=TRUE checkothers=TRUE
MatchedLengths "Schematic Matched Net Lengths_24" [InNet('HEXASPI_IO0')] p9: tolerance=20 checknetsindiffpair=FALSE checkdiffpairvsdiffpair=TRUE checkxsignals=TRUE checkothers=TRUE
MatchedLengths "Schematic Matched Net Lengths_23" [InNet('HEXASPI_CLK')] p10: tolerance=20 checknetsindiffpair=FALSE checkdiffpairvsdiffpair=TRUE checkxsignals=TRUE checkothers=TRUE
MatchedLengths "Schematic Matched Net Lengths_22" [InNet('HEXASPI_IO3')] p11: tolerance=20 checknetsindiffpair=FALSE checkdiffpairvsdiffpair=TRUE checkxsignals=TRUE checkothers=TRUE
MatchedLengths "Schematic Matched Net Lengths_21" [InNet('OCTOSPI_IO0')] p12: tolerance=20 checknetsindiffpair=FALSE checkdiffpairvsdiffpair=TRUE checkxsignals=TRUE checkothers=TRUE
MatchedLengths "Schematic Matched Net Lengths_20" [InNet('HEXASPI_IO12')] p13: tolerance=20 checknetsindiffpair=FALSE checkdiffpairvsdiffpair=TRUE checkxsignals=TRUE checkothers=TRUE
MatchedLengths "Schematic Matched Net Lengths_19" [InNet('HEXASPI_IO14')] p14: tolerance=20 checknetsindiffpair=FALSE checkdiffpairvsdiffpair=TRUE checkxsignals=TRUE checkothers=TRUE
MatchedLengths "Schematic Matched Net Lengths_18" [InNet('HEXASPI_IO9')] p15: tolerance=20 checknetsindiffpair=FALSE checkdiffpairvsdiffpair=TRUE checkxsignals=TRUE checkothers=TRUE
MatchedLengths "Schematic Matched Net Lengths_17" [InNet('OCTOSPI_IO7')] p16: tolerance=20 checknetsindiffpair=FALSE checkdiffpairvsdiffpair=TRUE checkxsignals=TRUE checkothers=TRUE
MatchedLengths "Schematic Matched Net Lengths_16" [InNet('OCTOSPI_IO1')] p17: tolerance=20 checknetsindiffpair=FALSE checkdiffpairvsdiffpair=TRUE checkxsignals=TRUE checkothers=TRUE
MatchedLengths "Schematic Matched Net Lengths_15" [InNet('HEXASPI_IO11')] p18: tolerance=20 checknetsindiffpair=FALSE checkdiffpairvsdiffpair=TRUE checkxsignals=TRUE checkothers=TRUE
MatchedLengths "Schematic Matched Net Lengths_14" [InNet('OCTOSPI_IO4')] p19: tolerance=20 checknetsindiffpair=FALSE checkdiffpairvsdiffpair=TRUE checkxsignals=TRUE checkothers=TRUE
MatchedLengths "Schematic Matched Net Lengths_13" [InNet('OCTOSPI_IO2')] p20: tolerance=20 checknetsindiffpair=FALSE checkdiffpairvsdiffpair=TRUE checkxsignals=TRUE checkothers=TRUE
MatchedLengths "Schematic Matched Net Lengths_12" [InNet('OCTOSPI_IO3')] p21: tolerance=20 checknetsindiffpair=FALSE checkdiffpairvsdiffpair=TRUE checkxsignals=TRUE checkothers=TRUE
MatchedLengths "Schematic Matched Net Lengths_11" [InNet('HEXASPI_IO15')] p22: tolerance=20 checknetsindiffpair=FALSE checkdiffpairvsdiffpair=TRUE checkxsignals=TRUE checkothers=TRUE
MatchedLengths "Schematic Matched Net Lengths_10" [InNet('HEXASPI_IO1')] p23: tolerance=20 checknetsindiffpair=FALSE checkdiffpairvsdiffpair=TRUE checkxsignals=TRUE checkothers=TRUE
MatchedLengths "Schematic Matched Net Lengths_9" [InNet('HEXASPI_IO7')] p24: tolerance=20 checknetsindiffpair=FALSE checkdiffpairvsdiffpair=TRUE checkxsignals=TRUE checkothers=TRUE
MatchedLengths "Schematic Matched Net Lengths_8" [InNet('HEXASPI_DQS0')] p25: tolerance=20 checknetsindiffpair=FALSE checkdiffpairvsdiffpair=TRUE checkxsignals=TRUE checkothers=TRUE
MatchedLengths "Schematic Matched Net Lengths_7" [InNet('OCTOSPI_DQS')] p26: tolerance=20 checknetsindiffpair=FALSE checkdiffpairvsdiffpair=TRUE checkxsignals=TRUE checkothers=TRUE
MatchedLengths "Schematic Matched Net Lengths_6" [InNet('HEXASPI_IO10')] p27: tolerance=20 checknetsindiffpair=FALSE checkdiffpairvsdiffpair=TRUE checkxsignals=TRUE checkothers=TRUE
MatchedLengths "Schematic Matched Net Lengths_5" [InNet('HEXASPI_IO13')] p28: tolerance=20 checknetsindiffpair=FALSE checkdiffpairvsdiffpair=TRUE checkxsignals=TRUE checkothers=TRUE
MatchedLengths "Schematic Matched Net Lengths_4" [InNet('HEXASPI_IO2')] p29: tolerance=20 checknetsindiffpair=FALSE checkdiffpairvsdiffpair=TRUE checkxsignals=TRUE checkothers=TRUE
MatchedLengths "Schematic Matched Net Lengths_3" [InNet('HEXASPI_IO6')] p30: tolerance=20 checknetsindiffpair=FALSE checkdiffpairvsdiffpair=TRUE checkxsignals=TRUE checkothers=TRUE
MatchedLengths "Schematic Matched Net Lengths_2" [InNet('OCTOSPI_CLK')] p31: tolerance=10 checknetsindiffpair=FALSE checkdiffpairvsdiffpair=TRUE checkxsignals=TRUE checkothers=TRUE
MaxMinImpedance "Schematic Impedance Constraint_10" [InNetClass('OCTOSPI')] p1: minimum=45.00 maximum=55.00
MaxMinImpedance "Schematic Impedance Constraint_25" [InNet('STLK_USB_CN_P')] p2: minimum=85.00 maximum=95.00
MaxMinImpedance "Schematic Impedance Constraint_23" [InNet('STLK_USB_N')] p3: minimum=85.00 maximum=95.00
MaxMinImpedance "Schematic Impedance Constraint_22" [InNet('STLK_USB_CN_N')] p4: minimum=85.00 maximum=95.00
MaxMinImpedance "Schematic Impedance Constraint_21" [InNet('STLK_USB_P')] p5: minimum=85.00 maximum=95.00
MaxMinImpedance "Schematic Impedance Constraint_20" [InNet('HEXASPI_NCS')] p6: minimum=50.00 maximum=60.00
MaxMinImpedance "Schematic Impedance Constraint_19" [InNet('HEXASPI_DQS0')] p7: minimum=50.00 maximum=60.00
MaxMinImpedance "Schematic Impedance Constraint_18" [InNet('HEXASPI_IO2')] p8: minimum=45.00 maximum=55.00
MaxMinImpedance "Schematic Impedance Constraint_17" [InNet('HEXASPI_IO6')] p9: minimum=45.00 maximum=55.00
MaxMinImpedance "Schematic Impedance Constraint_16" [InNet('HEXASPI_IO7')] p10: minimum=45.00 maximum=55.00
MaxMinImpedance "Schematic Impedance Constraint_15" [InNet('HEXASPI_IO0')] p11: minimum=45.00 maximum=55.00
MaxMinImpedance "Schematic Impedance Constraint_14" [InNet('HEXASPI_IO11')] p12: minimum=45.00 maximum=55.00
MaxMinImpedance "Schematic Impedance Constraint_13" [InNet('HEXASPI_IO12')] p13: minimum=45.00 maximum=55.00
MaxMinImpedance "Schematic Impedance Constraint_12" [InNet('HEXASPI_IO13')] p14: minimum=45.00 maximum=55.00
MaxMinImpedance "Schematic Impedance Constraint_11" [InNet('HEXASPI_IO4')] p15: minimum=45.00 maximum=55.00
MaxMinImpedance "Schematic Impedance Constraint_9" [InNet('HEXASPI_IO1')] p16: minimum=45.00 maximum=55.00
MaxMinImpedance "Schematic Impedance Constraint_8" [InNet('HEXASPI_IO15')] p17: minimum=45.00 maximum=55.00
MaxMinImpedance "Schematic Impedance Constraint_7" [InNet('HEXASPI_IO14')] p18: minimum=45.00 maximum=55.00
MaxMinImpedance "Schematic Impedance Constraint_6" [InNet('HEXASPI_IO10')] p19: minimum=45.00 maximum=55.00
MaxMinImpedance "Schematic Impedance Constraint_5" [InNet('HEXASPI_DQS1')] p20: minimum=45.00 maximum=55.00
MaxMinImpedance "Schematic Impedance Constraint_4" [InNet('HEXASPI_IO9')] p21: minimum=45.00 maximum=55.00
MaxMinImpedance "Schematic Impedance Constraint_3" [InNet('HEXASPI_CLK')] p22: minimum=45.00 maximum=55.00
MaxMinImpedance "Schematic Impedance Constraint_2" [InNet('HEXASPI_IO5')] p23: minimum=45.00 maximum=55.00
MaxMinImpedance "Schematic Impedance Constraint_1" [InNet('HEXASPI_IO3')] p24: minimum=45.00 maximum=55.00
MaxMinImpedance "Schematic Impedance Constraint" [InNet('HEXASPI_IO8')] p25: minimum=45.00 maximum=55.00
MinimumSolderMaskSliver [All] p1: minsoldermaskwidth=0.5
PlaneConnect [All] p1: planeconnectstyle=Relief reliefexpansion=20 reliefentries=4 reliefconductorwidth=10 reliefairgap=6
PolygonConnect PolygonConnect_via [IsVia] p1: connectstyle=Direct reliefconductorwidth=10 reliefentries=4 polygonreliefangle="90 Angle" airgapwidth=10
PolygonConnect [All] p2: connectstyle=Relief reliefconductorwidth=20 reliefentries=4 polygonreliefangle="90 Angle" airgapwidth=6
RoomDefinition Room_U24 [InComponentClass('Components Class 1')] p1: confinementstyle=ConfineIn formatcopy=TRUE lockcomponents=FALSE outline 815,1270 1060,1270 1060,1025 815,1025
RoomDefinition Room_U22 [InComponentClass('U_Power')] p2: confinementstyle=ConfineIn formatcopy=TRUE lockcomponents=FALSE outline 2427,1622 2965,1622 2965,1084 2427,1084
RoomDefinition U_ST-LinkV3EC [InComponentClass('U_ST-LinkV3EC')] p3: confinementstyle=ConfineIn formatcopy=TRUE lockcomponents=FALSE outline 2245,562.91 2500.9,562.91 2500.9,223.46 2245,223.46
RoomDefinition Room_U21 [InComponentClass('Components Class 4')] p4: confinementstyle=ConfineIn formatcopy=TRUE lockcomponents=FALSE outline 2868,580 3144,580 3144,224 2868,224
RoomDefinition Room_U14 [InComponentClass('Components Class 2')] p5: confinementstyle=ConfineIn formatcopy=TRUE lockcomponents=FALSE outline 4655,2420 5075,2420 5075,1990 4655,1990
RoutingLayers "Schematic Routing Layers_1" [InNetClass('HEXASPI')] p1: top layer_v5=TRUE mid layer 1_v5=TRUE mid layer 2_v5=TRUE mid layer 3_v5=TRUE mid layer 4_v5=TRUE bottom layer_v5=FALSE
RoutingLayers "Schematic Routing Layers" [InNetClass('OCTOSPI')] p2: top layer_v5=TRUE mid layer 1_v5=TRUE mid layer 2_v5=TRUE mid layer 3_v5=TRUE mid layer 4_v5=TRUE bottom layer_v5=FALSE
RoutingLayers [All] p3: top layer_v5=TRUE mid layer 1_v5=TRUE mid layer 2_v5=TRUE mid layer 3_v5=TRUE mid layer 4_v5=TRUE bottom layer_v5=TRUE
RoutingVias [All] p1: holewidth=10 width=20 viastyle="Through Hole" minholewidth=4 minwidth=10 maxholewidth=12 maxwidth=24
SilkToSilkClearance [All] p1: silktosilkclearance=0.5
SilkToSolderMaskClearance [IsPad] p1: minsilkscreentomaskgap=0.5 clearancetoexposedcopper=TRUE
SolderMaskExpansion [All] p1: expansion=4 istentingtop=FALSE
Width [All] p1: maxlimit=50 minlimit=3.5 preferedwidth=5 midlayer2_prefwidth=4 substack1={5D5844C5-C1B0-405F-A42B-4ABDA7DE1448} minimp=50.000000 maximp=50.000000 favimp=50.000000
21 further rules are at their usual default settings.

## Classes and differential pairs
component class "U_Arduino extension connectors": C126 CN11 CN12 CN14 CN15 LD12 Q3 R108 R120 R130 R150 SB24 SB25 SB26 SB27 SB56 SB58 SB59
component class "U_Audio Codec": C127 C128 C129 C130 C131 C132 C133 C134 C135 C137 C138 C139 C140 C141 C144 CN16 R127 R129 R131 R132 R145 R146 SB52 SB54 SB57 SB60 U24 U28
component class U_Ethernet: C49 C50 C91 C92 C98 C99 C100 C101 C102 C158 C159 C160 CN10 L1 R46 R47 R48 R85 R87 R89 R90 R92 R95 R96 R98 R99 R100 R102 R103 R104 R105 R107 R172 R173 R174 R175 SB69 SB70 U18 U19 U33 X4
component class "U_HexaSPI PSRAM": C42 C47 C110 C113 R115 SB67 U21
component class "U_LCD & Camera connectors": C15 C16 C18 C76 CN2 CN6 H5 H6 H7 H8 Q1 Q2 R17 R21 R29 R32 R57 R58 R61 R64 R65 SB19 SB34 TP1 TP2
component class U_Mechanical: H1 H2 H3 H4 HW1 HW2 HW8
component class "U_MEMs microphone": C1 C2 C3 CN1 R2 R7 R8 TP11 U2 U5
component class U_MicroSD: C13 C125 CN13 U3
component class "U_OctoSPI Flash": C14 C17 C19 C117 C119 C122 D1 R116 R117 R118 SB66 TP9 TP10 U23
component class U_Peripherals: CN3 CN4 LD1 LD2 LD3 LD4 Q9 Q10 R3 R4 R5 R6 R168 R169 R170 R171 SB1 SB2 SB3 SB4 SB5 SB6 SB7 SB8 SB9 SB10 SB11 SB12 SB13 SB14 SB15 SB16 SB17 SB18 SB51
component class U_Power: C86 C88 C89 C90 C93 C97 C103 C104 HW5 HW10 JP1 LD10 R69 R82 R91 R97 R101 SB21 SB23 TP3 TP5 TP6 TP7 TP8 U15 U17 U20
component class U_ST-LinkV3EC: C4 C51 C52 C53 C54 C55 C56 C57 C58 C59 C60 C61 C62 C63 C64 C65 C66 C67 C68 C69 C70 C71 C72 C73 C77 C78 C79 C80 C81 C82 C83 C84 C85 C87 C94 C95 C96 CN5 CN7 CN8 CN9 D3 D4 D5 D6 JP3 LD7 LD8 R9 R49 R50 R51 R52 R53 R54 R55 R56 R59 R60 R62 R63 R66 R67 R68 R71 R72 R73 R74 R75 R76 R77 R78 R79 R80 R83 R84 R86 R88 R93 R94 R177 SB22 SB71 TP4 U4 U8 U9 U10 U11 U12 U13 U14 U16 X1
component class "U_STM32 microcontroller IOs": B1 B2 C75 C107 C108 C109 JP6 R1 R44 R45 R110 R111 R112 R114 SB20 SB31 SB42 SB43 SB45 SB46 SB47 SB49 SB50 SB53 SB68 SB72 SB73 SB74 SB75 SB76 SB77 SW1 TP12 TP13 TP14 TP15 TP16 TP17 TP18 TP19 TP20 TP21 TP22 TP23 TP24 TP25 TP26 TP27 TP28 TP29 TP30 TP31 TP32 TP33 TP34 TP35 TP36 TP37 TP38 TP39 TP40 TP41 TP42 U6 U7 U22 X2 X3
component class "U_STM32 microcontroller power": C20 C21 C22 C23 C24 C25 C26 C27 C28 C29 C30 C31 C32 C33 C34 C35 C36 C37 C38 C39 C40 C41 C43 C44 C45 C46 C48 C105 C106 C111 C114 C115 C118 C120 C121 HW4 JP5 L4 R106 R109 SB28 SB29 SB30 SB32 SB33 SB35 SB36 SB37 SB38 SB39 SB40 SB41 SB44 SB48 SB55
component class "U_USB1 DRP": C136 C145 C146 C147 C150 C156 C157 CN18 CN19 LD6 Q4 Q5 Q8 R134 R135 R136 R147 R151 R152 R153 R155 R162 R163 R167 SB61 SB64 SB65 TP43 U26 U30 U31
component class "U_USB2 SNK": C5 C153 CN17 D7 LD5 Q6 Q7 R70 R113 R156 R158 R159 R161 R166 SB62 SB63 U27 U29 U32
net class HEXASPI: HEXASPI_CLK HEXASPI_DQS0 HEXASPI_DQS1 HEXASPI_IO0 HEXASPI_IO1 HEXASPI_IO2 HEXASPI_IO3 HEXASPI_IO4 HEXASPI_IO5 HEXASPI_IO6 HEXASPI_IO7 HEXASPI_IO8 HEXASPI_IO9 HEXASPI_IO10 HEXASPI_IO11 HEXASPI_IO12 HEXASPI_IO13 HEXASPI_IO14 HEXASPI_IO15 HEXASPI_NCS
net class OCTOSPI: OCTOSPI_CLK OCTOSPI_DQS OCTOSPI_IO0 OCTOSPI_IO1 OCTOSPI_IO2 OCTOSPI_IO3 OCTOSPI_IO4 OCTOSPI_IO5 OCTOSPI_IO6 OCTOSPI_IO7 OCTOSPI_NCS
component class "Components Class 1": U24
differential pair RD: +RD_P -RD_N
differential pair RX: +RX_P -RX_N
differential pair STLK_USB_CN: +STLK_USB_CN_P -STLK_USB_CN_N
differential pair STLK_USB: +STLK_USB_P -STLK_USB_N
differential pair TD: +TD_P -TD_N
differential pair TX: +TX_P -TX_N
differential pair USB1_CN_HS: +USB1_CN_HS_P -USB1_CN_HS_N
differential pair USB2_CN_FS: +USB2_CN_FS_P -USB2_CN_FS_N

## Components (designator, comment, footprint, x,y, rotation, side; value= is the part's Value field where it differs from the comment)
B1 "SW_BLACK_KSC321JLFS" SWI_C&K_KSC321JLFS_BLACK 5721.26,1110.25 r270 top value=KSC321JLFS
B2 "SW_BLUE_KSC721JLFS" SWI_C&K_KSC721JLFS_BLUE 5721.26,604.77 r270 top value=KSC721JLFS
C1 "Capacitor" C0402 439,2842 r180 bottom value=100nF
C2 "Capacitor" C0402 478,2998 r90 bottom value=1uF
C3 "Capacitor" C0402 442.55,2998.35 r90 bottom value=100nF
C4 "Capacitor" C0603 5330,1874.99 r270 bottom value=100nF
C5 "Capacitor" C0603 680,1620 r0 bottom value=10nF
C13 "Capacitor" C0603 1940,3180 r180 top value=4.7uF
C14 "Capacitor" C0402 2245,445.02 r90 top value=100nF
C15 "Capacitor" C0402 2347.87,2751.24 r90 top value=100nF
C16 "Capacitor" C0805 2407.89,2351.22 r0 top value=10uF
C17 "Capacitor" C0402 2395.02,314.99 r0 top value=100nF
C18 "Capacitor" C0402 2407.9,2421.22 r180 top value=100nF
C19 "Capacitor" C0402 2460.02,525 r180 top value=100nF
C20 "Capacitor" C0402 2464.02,1330 r0 top value=100nF
C21 "Capacitor" C0402 2464.02,1366 r0 top value=100nF
C22 "Capacitor" C0402 2530.02,1370 r0 top value=100nF
C23 "Capacitor" C0402 2592.01,1282 r0 top value=100nF
C24 "Capacitor" C0402 2600.02,1370 r180 top value=100nF
C25 "Capacitor" C0402 2622.01,1425 r135 top value=1uF
C26 "Capacitor" C0402 2640,1480.01 r270 top value=100nF
C27 "Capacitor" C0603 2660,1580 r180 top value=1uF
C28 "Capacitor" C0402 2658.02,1267 r180 top value=100nF
C29 "Capacitor" C0402 2654,1170.01 r90 top value=100nF
C30 "Capacitor" C0402 2699.01,1392 r45 top value=100nF
C31 "Capacitor" C0402 2709.01,1310 r315 top value=100nF
C32 "Capacitor" C0402 2703,1510.01 r270 top value=100nF
C33 "Capacitor" C0402 2712.65,1166.15 r90 top value=100nF
C34 "Capacitor" C0402 2712.65,1236.15 r270 top value=100nF
C35 "Capacitor" C0402 2738.01,1368 r45 top value=100nF
C36 "Capacitor" C0402 2768.02,1462.01 r225 top value=100nF
C37 "Capacitor" C0402 2770.01,1246 r315 top value=1uF
C38 "Capacitor" C0402 2803.01,1431 r225 top value=100nF
C39 "Capacitor" C0402 2813.02,1279 r180 top value=100nF
C40 "Capacitor" C0402 2816.01,1363 r180 top value=100nF
C41 "Capacitor" C0402 2891.01,1362 r180 top value=100nF
C42 "Capacitor" C0402 2880,438 r90 top value=100nF
C43 "Capacitor" C0402 2960.01,1300 r0 top value=10uF
C44 "Capacitor" C0402 3165,1415 r270 top value=220pF
C45 "Capacitor" C0402 3035,1320 r270 top value=1uF
C46 "Capacitor" C0402 3071,1249 r90 top value=100nF
C47 "Capacitor" C0402 3100.02,520 r180 top value=100nF
C48 "Capacitor" C0402 3100,1330 r90 top value=1uF
C49 "Capacitor" C0402 4475.02,1135 r0 top value=100nF
C50 "Capacitor" C0402 4516.83,1644.84 r180 top value=100nF
C51 "Capacitor" C0402 4645,2350 r270 top value=100nF
C52 "Capacitor" C0402 4689.67,2117.65 r180 top value=100nF
C53 "Capacitor" C0402 4691,2198.39 r180 top value=100nF
C54 "Capacitor" C0603 4689.94,2269.94 r270 top value=4.7uF
C55 "Capacitor" C0402 4695,2350 r270 top value=100nF
C56 "Capacitor" C0402 4705.18,2024.06 r270 top value=100nF
C57 "Capacitor" C0402 4759.53,2023.19 r270 top value=100nF
C58 "Capacitor" C0402 4775.43,2234.62 r270 top value=100nF
C59 "Capacitor" C0402 4780,2395 r90 top value=10nF
C60 "Capacitor" C0402 4799.53,2023.16 r270 top value=100nF
C61 "Capacitor" C0402 4820,2395 r90 top value=10nF
C62 "Capacitor" C0402 4855.33,2023.26 r270 top value=100nF
C63 "Capacitor" C0402 4865.1,2394.59 r90 top value=100nF
C64 "Capacitor" C0402 4895.33,2023.31 r270 top value=100nF
C65 "Capacitor" C0402 4905.05,2394.67 r90 top value=100nF
C66 "Capacitor" C0603 4945,2020 r90 top value=1uF
C67 "Capacitor" C0402 4946.94,2394.51 r90 top value=100nF
C68 "Capacitor" C0402 4956.19,2223.4 r270 top value=100nF
C69 "Capacitor" C0603 5022.76,2305.91 r180 top value=2.2uF
C70 "Capacitor" C0603 5063.12,2127.51 r180 top value=2.2uF
C71 "Capacitor" C0402 5050.85,2215.07 r0 top value=100nF
C72 "Capacitor" C0402 5051.1,2178.23 r0 top value=100nF
C73 "Capacitor" C0402 5051.1,2257.33 r0 top value=100nF
C75 "Capacitor" C0402 3114,1196 r180 top value=10nF
C76 "Capacitor" C0402 5605.02,3275 r0 top value=1uF
C77 "Capacitor" C0402 5472.77,2440.9 r180 bottom value=100pF
C78 "Capacitor" C0402 5320,2015 r270 bottom value=100nF
C79 "Capacitor" C0603 5425,1935 r180 bottom value=10uF
C80 "Capacitor" C0603 5290,1685 r180 bottom value=10uF
C81 "Capacitor" C0402 5182.77,1410.9 r0 bottom value=100nF
C82 "Capacitor" C0603 5162.88,2316.22 r0 bottom value=2.2uF
C83 "Capacitor" C0402 5162.9,2206.22 r0 bottom value=20pF
C84 "Capacitor" C0402 5175,2005 r90 bottom value=10nF
C85 "Capacitor" C0805 5080,1470 r180 bottom value=2.2uF
C86 "Capacitor" C0603 5100,1155.01 r270 bottom value=4.7uF
C87 "Capacitor" C0603 5070,1585 r180 bottom value=10uF
C88 "Capacitor" C0603 4990,1050 r180 bottom value=4.7uF
C89 "Capacitor" C0402 4983.03,1270 r180 bottom value=100nF
C90 "Capacitor" C0402 4746.02,2814.8 r90 bottom value=100nF
C91 "Capacitor" C0402 4635.01,985 r180 top value=100nF
C92 "Capacitor" C0402 4320.01,985 r0 top value=100nF
C93 "Capacitor" C0603 4613.98,2705.22 r180 bottom value=4.7uF
C94 "Capacitor" C0402 4605.01,2305 r0 bottom value=100nF
C95 "Capacitor" C0402 4610,2150 r90 bottom value=5.6pF
C96 "Capacitor" C0402 4610,2220 r90 bottom value=5.6pF
C97 "Capacitor" C0603 4471.04,2854.77 r180 bottom value=4.7uF
C98 "Capacitor" C0402 4385.75,1461.11 r90 bottom value=100nF
C99 "Capacitor" C0402 4380.75,1686.11 r270 bottom value=1uF
C100 "Capacitor" C0402 4690.01,1405 r180 bottom value=100nF
C101 "Capacitor" C0402 4340.75,1686.11 r270 bottom value=470pF
C102 "Capacitor" C0603 4690,1355 r0 bottom value=10uF
C103 "Capacitor" C0805 4140.01,1675 r180 bottom value=10uF
C104 "Capacitor" C0805 3840,1210.01 r90 bottom value=10uF
C105 "Capacitor" C0603 3210,1230 r0 bottom value=4.7uF
C106 "Capacitor" C0603 3345,1390 r0 bottom value=10uF
C107 "Capacitor" C0402 3355,1095 r90 bottom value=100nF
C108 "Capacitor" C0402 3240.87,1531.56 r90 bottom value=2.7pF
C109 "Capacitor" C0402 3240.87,1611.56 r270 bottom value=2.7pF
C110 "Capacitor" C0603 3205,505.01 r90 bottom value=4.7uF
C111 "Capacitor" C0603 2935,805 r90 bottom value=4.7uF
C113 "Capacitor" C0603 2810,425.02 r90 bottom value=4.7uF
C114 "Capacitor" C0603 2253.56,993 r180 bottom value=2.2uF
C115 "Capacitor" C0603 2675,916.44 r90 bottom value=2.2uF
C117 "Capacitor" C0603 2570,505.01 r90 bottom value=4.7uF
C118 "Capacitor" C0603 2365,860 r90 bottom value=4.7uF
C119 "Capacitor" C0603 2320,179.99 r0 bottom value=4.7uF
C120 "Capacitor" C0603 2772,1813.56 r270 bottom value=2.2uF
C121 "Capacitor" C0603 2266.88,1469 r0 bottom value=2.2uF
C122 "Capacitor" C0603 2152.52,438.2 r90 bottom value=4.7uF
C125 "Capacitor" C0402 1850,2950.01 r90 bottom value=100nF
C126 "Capacitor" C0402 1494.75,2041.22 r0 bottom value=100nF
C127 "Capacitor" C0603 1120,1055 r180 bottom value=4.7uF
C128 "Capacitor" C0402 1115,1185 r180 bottom value=100nF
C129 "Capacitor" C0402 765,1045 r0 bottom value=100nF
C130 "Capacitor" C0603 1032.13,933.94 r270 bottom value=2.2uF
C131 "Capacitor" C0603 982.13,933.94 r270 bottom value=2.2uF
C132 "Capacitor" C0603 1082.13,933.94 r270 bottom value=2.2uF
C133 "Capacitor" C0603 665,1095 r180 bottom value=4.7uF
C134 "Capacitor" C0603 765,1150 r0 bottom value=4.7uF
C135 "Capacitor" C0603 765,1200 r0 bottom value=4.7uF
C136 "Capacitor" C0402 1150.02,2485 r180 bottom value=10pF
C137 "Capacitor" C0603 915,1310 r90 bottom value=1uF
C138 "Capacitor" C0603 855,1310 r90 bottom value=1uF
C139 "Capacitor" C0603 1117.13,1145.79 r180 bottom value=2.2uF
C140 "Capacitor" C0402 870,980 r270 bottom value=100nF
C141 "Capacitor" C0402 920,980 r270 bottom value=100nF
C144 "Capacitor" C0402 1115,1100 r180 bottom value=100nF
C145 "Capacitor" C0603 1000,2344.6 r0 bottom value=100nF
C146 "Capacitor" C0402 1000.02,2294.6 r180 bottom value=560pF
C147 "Capacitor" C0402 997.75,2399.6 r180 bottom value=560pF
C150 "Capacitor" C0603 870,2740.01 r270 bottom value=10nF
C153 "Capacitor" C0603 640,1561.22 r180 bottom value=100nF
C156 "Capacitor" C0603_H0P8 457.76,2250.91 r90 top value=2.2uF
C157 "Capacitor" C0603 555,2740.01 r270 bottom value=100nF
C158 "Capacitor" C1206_H1P6 4940,385 r90 bottom value=1nF
C159 "Capacitor" C0402 4380.99,1540 r90 bottom value=8.2pF
C160 "Capacitor" C0402 4380,1615 r270 bottom value=8.2pF
CN1 "Socket 10x2" CON_FCI_20021311-XXX20XXLF 125,2926.22 r270 top
CN2 "Header 25x2" CON_SAMTEC_FLE-125-01-G-DV 2952.88,2573.76 r180 top
CN3 "Socket 10X2 STMod+" CON_SAMTEC_SQT-110-01-F-D-RA__STMOD+ 3618.37,3439.62 r180 top value="Socket 10X2"
CN4 "Socket 6X2 PMOD" CON_SAMTEC_SSW-106-02-F-D-RA__PMOD 4640,3335 r180 top value="Socket 6X2"
CN5 "Tag-10-C" CON_TAG-C_TC2050-IDC-NL 5701.3,1601.22 r90 top value="Header 5x2"
CN6 "FPU330ZH-BT1D3-CA" CON_TOWNES_FPU330ZH-BT1D3-CA_P050 5791.38,2954.25 r90 top value=Socket_FFC/FPC_FPU330ZH-BT1D3-CA
CN7 "USB_TYPE_C_Receptacle" CON_USB-TYPEC_AMPHENOL_12401826E412A 5609.99,2299.99 r270 bottom value=USB_C_12401826E412A
CN8 "Header 10x2" CON_SAMTEC_FTSH-110-01-L-DV 5110.01,2916 r90 bottom
CN9 "Header 4x1" CON_SAMTEC_TSW-104-07-G-S 4990,1765 r0 bottom
CN10 "RJ45_KRJ-CB4.2GYZNL" CON_RJ45_DGKYD_KRJ-CB4.2GYZNL 4502.76,0 r180 bottom
CN11 "Socket 6x1" CON_SAMTEC_SSW-106-22-X-S-VS 3606.5,784.25 r90 bottom
CN12 "Socket 8x1" CON_SAMTEC_SSW-108-22-X-S-VS 3606.5,1584.25 r90 bottom
CN13 "microSD-PJS008-2003" CON_MICROSD_YAMAICHI_PJS008-2003-1 1841.82,3796.39 r90 bottom value=uSD-Card_PJS008-2003-1
CN14 "Socket 8x1" CON_SAMTEC_SSW-108-22-X-S-VS 1706.5,884.25 r270 bottom
CN15 "Socket 10x1" CON_SAMTEC_SSW-110-22-X-S-VS 1704.89,1844.25 r270 bottom
CN16 "Jack_PJ3028B-3_4P" CON_PHONE-JACK-3P5_HY_PJ3028B 1101.59,1.21 r90 bottom value="Jack_ Socket-Stereo_PJ3028B-3_4P"
CN17 "USB_TYPE_C_Receptacle" CON_USB-TYPEC_AMPHENOL_12401826E412A 292.77,1580.99 r90 bottom value=USB_C_12401826E412A
CN18 "USB_TYPE_C_Receptacle" CON_USB-TYPEC_AMPHENOL_12401826E412A 292.77,2370 r90 bottom value=USB_C_12401826E412A
CN19 "Jumper_Header 2x1" CON_SAMTEC_TSW-102-07-G-S 573,3070 r90 bottom value="Header 2x1"
D1 "SCHOTTKY_1A_2K" DIO_SOD523_1A_2K 2494.99,190 r270 bottom value=BAT54KFILM
D3 "SCHOTTKY_1A_2K" DIO_SOD523_1A_2K 5085,1359.99 r90 bottom value=BAT54KFILM
D4 "SCHOTTKY_1A_2K" DIO_SOD523_1A_2K 5030,1359.99 r90 bottom value=BAT54KFILM
D5 "SCHOTTKY_1A_2K" DIO_SOD523_1A_2K 4975,1359.99 r90 bottom value=BAT54KFILM
D6 "SCHOTTKY_1A_2K" DIO_SOD523_1A_2K 4910,1359.99 r90 bottom value=BAT54KFILM
D7 "SCHOTTKY_1A_2K" DIO_SOD523_1A_2K 520.01,1501.22 r0 bottom value=BAT54KFILM
H1 "POSITION HOLE" PTH_350_700 200,205.9 r0 top
H2 "POSITION HOLE" PTH_350_700 200,3573.62 r0 top
H3 "POSITION HOLE" PTH_350_700 5705.51,3573.61 r0 top
H4 "POSITION HOLE" PTH_350_700 5705.52,205.9 r0 top
H5 "POSITION HOLE" PTH_450_900 5245.79,205.9 r180 bottom value=N/A
H6 "POSITION HOLE" PTH_450_900 5245.79,3573.61 r180 bottom value=N/A
H7 "POSITION HOLE" PTH_450_900 659.96,205.9 r180 bottom value=N/A
H8 "POSITION HOLE" PTH_450_900 659.96,3573.61 r180 bottom value=N/A
HW1 "STICKER_PRODUCT" STICKER_PRODUCT_25X9 3805,3106 r180 bottom value="Sticker product"
HW2 "STICKER_BOARD" STICKER_BOARD_25X9 2696,3102 r180 bottom value="Sticker board"
JP1 "Jumper_Header 4x2" CON_SAMTEC_TSM-104-01-X-DV 5654.64,700 r270 bottom value=Jumper_Header_4x2
JP3 "Jumper_Header 2x1" CON_SAMTEC_TSW-102-07-G-S 4477.07,2410.5 r90 bottom value="Header 2x1"
JP5 "Jumper_Header 2x1 Fitted" CON_SAMTEC_TSW-102-07-G-S 3327,2226 r180 bottom value="Header 2x1"
JP6 "Jumper_Header 3x1 Fitted 1-2" CON_SAMTEC_TSW-103-07-F-S 2660,3620 r180 bottom value="Header 3x1"
L1 "BEAD" L0603 4695.01,1285 r0 bottom value="600R @100MHz"
L4 "Inductor" IND_2016_MURATA_LQM2MPN2R2NG0 3185,1405 r90 bottom value=2.2uH
LD1 "LED_green" LED_0603_OSRAM_LG-Q396-PS-35_GREEN_1A2K_H0P4 185.5,650 r0 top value=GREEN
LD2 "LED_orange" LED_0603_OSRAM_LO-Q976-PS-25_ORANGE_1A2K_H0P8 185.5,730 r0 top value=ORANGE
LD3 "LED_red" LED_0603_VISHAY_VLMS1300-GS08_RED_1A2K_H0P8 185.02,815 r0 top value=RED
LD4 "LED_blue" LED_0603_OSRAM_LB-Q39G-L2OO-35-1_BLUE_1A2K_H0P4 185.02,890 r0 top value=BLUE
LD5 "LED_green" LED_0603_OSRAM_LG-Q396-PS-35_GREEN_1A2K_H0P4 420,1905 r270 top value=GREEN
LD6 "LED_green" LED_0603_OSRAM_LG-Q396-PS-35_GREEN_1A2K_H0P4 420,2095 r270 top value=GREEN
LD7 "LED_BICOLOR" LED_BI-GR_WE-150141SV73110 5634.01,1955.99 r0 top value="Green / Red"
LD8 "LED_BICOLOR" LED_BI-GR_WE-150141SV73110 5798.01,1955.99 r0 top value="Green / Red"
LD10 "LED_green" LED_0603_OSRAM_LG-Q396-PS-35_GREEN_1A2K_H0P4 5364.99,1008 r0 bottom value=GREEN
LD12 "LED_green" LED_0603_OSRAM_LG-Q396-PS-35_GREEN_1A2K_H0P4 1080,1960.01 r90 bottom value=GREEN
Q1 "BSN20" MOS_SOT23 5605.5,3032.22 r90 bottom value=BSN20BK
Q2 "BSN20" MOS_SOT23 5604.67,3181.19 r90 bottom value=BSN20BK
Q3 "BSN20" MOS_SOT23 1210.02,1960.01 r270 bottom value=BSN20BK
Q4 "STL40DN3LLH5" PowerFLAT_5x6 1020,2819.29 r0 bottom
Q5 "STL40DN3LLH5" PowerFLAT_5x6 720,2819.61 r0 bottom
Q6 "STL11N3LLH6" MOS_POWERFLAT_3P3X3P3_P065 650,1711.22 r270 bottom
Q7 "9013-SOT23" NPN_SOT23 550.01,1900 r270 bottom value="NPN SOT23"
Q8 "9013-SOT23" NPN_SOT23 550.01,2090 r270 bottom value="NPN SOT23"
Q9 "9013-SOT23" NPN_SOT23 303.34,630.76 r90 bottom value="NPN SOT23"
Q10 "9013-SOT23" NPN_SOT23 303.34,765.57 r90 bottom value="NPN SOT23"
R1 "Resistor" R0402 227.91,1204.68 r0 top value=10K
R2 "Resistor" R0402 441.93,3073.83 r90 bottom value=0R
R3 "Resistor" R0402 300.02,815 r180 top value=680R
R4 "Resistor" R0402 300.02,890 r180 top value=510R
R5 "Resistor" R0402 300.5,650 r180 top value=510R
R6 "Resistor" R0402 300.5,730 r180 top value=300R
R7 "Resistor" R0402 425,2825 r270 top value=10K
R8 "Resistor" R0402 275,3033.7 r90 bottom value=10K
R9 "Resistor" R0402 4760,1920 r90 bottom value=10K
R17 "Resistor" R0603 2360,2260.01 r90 top value=0R
R21 "Resistor" R0603 2460,2260.01 r90 top value=0R
R29 "Resistor" R0402 2597.87,2753.51 r90 top value=0R
R32 "Resistor" R0402 2657.87,2751.24 r90 top value=0R
R44 "Resistor" R0402 3220.02,1700 r180 top value=1K5
R45 "Resistor" R0402 3220.02,1750 r180 top value=1K5
R46 "Resistor" R0402 4442.56,1756.11 r270 top value=33R
R47 "Resistor" R0402 4487.56,1756.11 r270 top value=33R
R48 "Resistor" R0402 4585.75,1756.11 r90 top value=10K
R49 "Resistor" R0402 4740,2395 r90 top value=33R
R50 "Resistor" R0402 4775,2160 r90 top value=10K
R51 "Resistor" R0402 4810,1920 r270 bottom value=0R
R52 "Resistor" R0402 4917.76,1920.91 r270 bottom value=0R
R53 "Resistor" R0402 5467.76,2350.91 r0 top value=100K
R54 "Resistor" R0402 5467.76,2200.91 r0 top value=100K
R55 "Resistor" R0402 4647.76,2490.91 r90 bottom value=0R
R56 "Resistor" R0402 4860,1920 r270 bottom value=33R
R57 "Resistor" R0402 5605.02,3185 r180 top value=0R
R58 "Resistor" R0402 5605.02,3230 r180 top value=0R
R59 "Resistor" R0603 5830,1910 r270 bottom value=330R
R60 "Resistor" R0402 5770,1910 r270 bottom value=1K
R61 "Resistor" R0402 5717,3170.74 r270 bottom value=10K
R62 "Resistor" R0603 5665,1910 r270 bottom value=330R
R63 "Resistor" R0402 5605,1910 r270 bottom value=1K
R64 "Resistor" R0402 5498,3045.01 r270 bottom value=10K
R65 "Resistor" R0402 5497.95,3201.19 r270 bottom value=10K
R66 "Resistor" R0402 5410.01,1500 r180 bottom value=100K
R67 "Resistor" R0402 5255.01,1800 r180 bottom value=5K1
R68 "Resistor" R0402 5410.01,1620 r180 bottom value=100K
R69 "Resistor" R0603 5334,926 r90 bottom value=1K2
R70 "Resistor" R0603 865,1855 r180 bottom value=33K
R71 "Resistor" R0402 5467.76,2200.9 r180 bottom value=5K1
R72 "Resistor" R0402 5467.76,2350.9 r180 bottom value=5K1
R73 "Resistor" R0402 4992.76,2390.91 r90 top value=33R
R74 "Resistor" R0402 5037.76,2390.91 r90 top value=33R
R75 "Resistor" R0402 5275,1880 r270 bottom value=3K
R76 "Resistor" R0402 5230,1880 r270 bottom value=3K9
R77 "Resistor" R0402 5185,1880 r270 bottom value=1K3
R78 "Resistor" R0402 5162.9,2156.22 r0 bottom value=100R
R79 "Resistor" R0402 5162.9,2256.22 r0 bottom value=3K
R80 "Resistor" R0402 5140,1880 r270 bottom value=1K8
R82 "Resistor" R0402 4895,1198.02 r90 bottom value=10K
R83 "Resistor" R0603 4805,1410 r270 bottom value=47K
R84 "Resistor" R0603 4805,1525 r270 bottom value=27K
R85 "Resistor" R0402 4815,525.01 r270 bottom value=10K
R86 "Resistor" R0402 4769.18,2490.53 r90 bottom value=10K
R87 "Resistor" R0402 4760.76,525.73 r270 bottom value=270R
R88 "Resistor" R0402 4719.18,2490.53 r90 bottom value=5K1
R89 "Resistor" R0402 4680.77,1606.09 r180 bottom value=33R
R90 "Resistor" R0402 4680.77,1656.09 r0 bottom value=10K
R91 "Resistor" R0402 4636.05,2894.77 r0 bottom value=10K
R92 "Resistor" R0402 4635.75,1756.11 r90 bottom value=1K5
R93 "Resistor" R0402 4605.33,2381.7 r180 bottom value=10K
R94 "Resistor" R0402 4605.33,2428.95 r180 bottom value=10K
R95 "Resistor" R0402 4615,1385.01 r270 bottom value=49R9
R96 "Resistor" R0402 4585.75,1756.11 r270 bottom value=33R
R97 "Resistor" R0603 4546.02,2774.8 r270 bottom value=27K
R98 "Resistor" R0402 4555,1385.01 r270 bottom value=49R9
R99 "Resistor" R0402 4535.75,1756.11 r90 bottom value=10K
R100 "Resistor" R0402 4510,1385.01 r270 bottom value=49R9
R101 "Resistor" R0603 4471.04,2794.77 r0 bottom value=56K
R102 "Resistor" R0402 4487.56,1756.11 r90 bottom value=10K
R103 "Resistor" R0402 4450,1385.01 r270 bottom value=49R9
R104 "Resistor" R0402 4442.56,1756.11 r90 bottom value=10K
R105 "Resistor" R0402 4405,1385.01 r270 bottom value=12K1
R106 "Resistor" R0603 3345,1210 r180 bottom value=0R
R107 "Resistor" R0402 4195.76,525.73 r270 bottom value=270R
R108 "Resistor" R0402 3805.02,1935 r0 bottom value=1K
R109 "Resistor" R0603 3345,1275 r180 bottom value=0R
R110 "Resistor" R0402 3355,1020 r90 bottom value=10K
R111 "Resistor" R0402 3184.01,1549.25 r180 bottom value=0R
R112 "Resistor" R0402 3184.01,1593.93 r180 bottom value=0R
R113 "Resistor" R0603 975,1855 r180 bottom value=62K
R114 "Resistor" R0402 3180.9,1080.51 r180 bottom value=51R
R115 "Resistor" R0402 2970.01,199.99 r180 bottom value=10K
R116 "Resistor" R0402 2554.83,298.19 r0 bottom value=10K
R117 "Resistor" R0402 2412.52,185.93 r270 bottom value=10K
R118 "Resistor" R0402 2177.76,340.9 r270 bottom value=10K
R120 "Resistor" R0402 1495.02,2095 r180 bottom value=0R
R127 "Resistor" R0603 1117.56,1240 r0 bottom value=0R
R129 "Resistor" R0603 1117.56,1290 r0 bottom value=0R
R130 "Resistor" R0402 1320,1960.01 r90 bottom value=1M
R131 "Resistor" R0603 1117.56,1340 r0 bottom value=0R
R132 "Resistor" R0402 762.13,1095.79 r0 bottom value=2K2
R134 "Resistor" R0603 862.76,2530.91 r180 top value=22mR
R135 "Resistor" R0603 1150,2540 r180 bottom value=49K9
R136 "Resistor" R0603 1150,2615 r0 bottom value=330K
R145 "Resistor" R0603 860,880 r90 bottom value=20R
R146 "Resistor" R0603 920,880 r90 bottom value=20R
R147 "Resistor" R0402 1025,2456.91 r90 bottom value=2K4
R150 "Resistor" R0402 1015,1960.01 r90 bottom value=330R
R151 "Resistor" R0402 975,2456.91 r270 bottom value=10K
R152 "Resistor" R0402 899.12,2209.73 r270 bottom value=10K
R153 "Resistor" R0402 854.12,2209.73 r90 bottom value=0R
R155 "Resistor" R0402 804.12,2209.73 r90 bottom value=0R
R156 "Resistor" R0402 785,1441.24 r270 bottom value=2K4
R158 "Resistor" R0603 702.49,1854.3 r180 bottom value=47K
R159 "Resistor" R0402 720,1441.24 r270 bottom value=10K
R161 "Resistor" R0603 677.47,1959.32 r90 bottom value=10K
R162 "Resistor" R0603 587.76,2250.91 r90 top value=10K
R163 "Resistor" R0603 512.76,2250.91 r270 top value=47K
R166 "Resistor" R0402 365,1915 r90 bottom value=270R
R167 "Resistor" R0402 365,2090 r90 bottom value=270R
R168 "Resistor" R0603 185,628.17 r270 bottom value=100K
R169 "Resistor" R0603 185,758.17 r270 bottom value=100K
R170 "Resistor" R0603 125,760.73 r270 bottom value=47K
R171 "Resistor" R0603 120,628.17 r270 bottom value=47K
R172 "Resistor" R0402 4475.01,645 r180 top value=75R
R173 "Resistor" R0402 4475.01,600 r180 top value=75R
R174 "Resistor" R0402 4660,625 r270 top value=75R
R175 "Resistor" R0402 4610,625 r270 top value=75R
R177 "Resistor" R0402 5210,2065 r0 bottom value=100K
SB1 "SB_OFF" SOLDER-BRIDGE_R0603-0R 3099.31,3194.75 r90 top value="Solder Bridge OFF"
SB2 "SB_ON" SOLDER-BRIDGE_R0603-0R 3159.31,3194.75 r90 top value="Solder Bridge ON"
SB3 "SB_OFF" SOLDER-BRIDGE_R0603-0R 1843,2806 r90 top value="Solder Bridge OFF"
SB4 "SB_ON" SOLDER-BRIDGE_R0603-0R 3279.31,3194.74 r270 top value="Solder Bridge ON"
SB5 "SB_OFF" SOLDER-BRIDGE_R0603-0R 3339.31,3194.75 r90 top value="Solder Bridge OFF"
SB6 "SB_ON" SOLDER-BRIDGE_R0603-0R 3399.31,3194.75 r90 top value="Solder Bridge ON"
SB7 "SB_OFF" SOLDER-BRIDGE_R0603-0R 3459.31,3194.44 r90 top value="Solder Bridge OFF"
SB8 "SB_ON" SOLDER-BRIDGE_R0603-0R 3519.31,3194.75 r90 top value="Solder Bridge ON"
SB9 "SB_ON" SOLDER-BRIDGE_R0603-0R 3579.31,3193.68 r270 top value="Solder Bridge ON"
SB10 "SB_OFF" SOLDER-BRIDGE_R0603-0R 1791,2805.38 r90 top value="Solder Bridge OFF"
SB11 "SB_OFF" SOLDER-BRIDGE_R0603-0R 1946,2805.38 r90 top value="Solder Bridge OFF"
SB12 "SB_ON" SOLDER-BRIDGE_R0603-0R 3759.31,3193.68 r270 top value="Solder Bridge ON"
SB13 "SB_OFF" SOLDER-BRIDGE_R0603-0R 1998,2806.38 r90 top value="Solder Bridge OFF"
SB14 "SB_ON" SOLDER-BRIDGE_R0603-0R 3879.31,3193.68 r270 top value="Solder Bridge ON"
SB15 "SB_OFF" SOLDER-BRIDGE_R0603-0R 2050,2806.38 r90 top value="Solder Bridge OFF"
SB16 "SB_ON" SOLDER-BRIDGE_R0603-0R 4004.31,3193.99 r270 top value="Solder Bridge ON"
SB17 "SB_OFF" SOLDER-BRIDGE_R0603-0R 1895,2806 r90 top value="Solder Bridge OFF"
SB18 "SB_ON" SOLDER-BRIDGE_R0603-0R 4124.31,3193.68 r270 top value="Solder Bridge ON"
SB19 "SB_OFF" SOLDER-BRIDGE_R0603-0R 5575.33,2905 r180 top value="Solder Bridge OFF"
SB20 "SB_ON" SOLDER-BRIDGE_R0603-0R 3379.16,2061.94 r270 bottom value="Solder Bridge ON"
SB21 "SB_ON" SOLDER-BRIDGE_R0603-0R 5185.02,1125 r0 bottom value="Solder Bridge ON"
SB22 "SB_ON" SOLDER-BRIDGE_R0603-0R 5185.02,1330 r0 bottom value="Solder Bridge ON"
SB23 "SB_ON" SOLDER-BRIDGE_R0603-0R 4456.04,2699.77 r180 bottom value="Solder Bridge ON"
SB24 "SB_OFF" SOLDER-BRIDGE_R0603-0R 3826.32,471.22 r180 bottom value="Solder Bridge OFF"
SB25 "SB_ON" SOLDER-BRIDGE_R0603-0R 3824.74,541.22 r180 bottom value="Solder Bridge ON"
SB26 "SB_ON" SOLDER-BRIDGE_R0603-0R 3824.74,631.22 r180 bottom value="Solder Bridge ON"
SB27 "SB_OFF" SOLDER-BRIDGE_R0603-0R 3824.74,701.22 r180 bottom value="Solder Bridge OFF"
SB28 "SB_ON" SOLDER-BRIDGE_R0603-0R 3210,1425 r90 top value="Solder Bridge ON"
SB29 "SB_ON" SOLDER-BRIDGE_R0603-0R 3350,1335 r180 bottom value="Solder Bridge ON"
SB30 "SB_ON" SOLDER-BRIDGE_R0603-0R 3205,1715 r180 bottom value="Solder Bridge ON"
SB31 "SB_ON" SOLDER-BRIDGE_R0603-0R 3179.16,2061.93 r270 bottom value="Solder Bridge ON"
SB32 "SB_OFF" SOLDER-BRIDGE_R0603-0R 3030,1835 r180 bottom value="Solder Bridge OFF"
SB33 "SB_ON" SOLDER-BRIDGE_R0603-0R 2910,1879.99 r270 bottom value="Solder Bridge ON"
SB34 "SB_ON" SOLDER-BRIDGE_R0603-0R 3005,2780.02 r90 bottom value="Solder Bridge ON"
SB35 "SB_ON" SOLDER-BRIDGE_R0603-0R 3030,1910 r180 bottom value="Solder Bridge ON"
SB36 "SB_ON" SOLDER-BRIDGE_R0402-0R 3100,1409.99 r90 bottom value="0 ohm"
SB37 "SB_ON" SOLDER-BRIDGE_R0603-0R 3085,1425 r90 top value="Solder Bridge ON"
SB38 "SB_ON" SOLDER-BRIDGE_R0402-0R 2875,797.05 r90 bottom value="0 ohm"
SB39 "SB_OFF" SOLDER-BRIDGE_R0603-0R 3015,1425 r90 top value="Solder Bridge OFF"
SB40 "SB_ON" SOLDER-BRIDGE_R0603-0R 2262.68,1055 r0 bottom value="Solder Bridge ON"
SB41 "SB_ON" SOLDER-BRIDGE_R0603-0R 2840,1880 r90 bottom value="Solder Bridge ON"
SB42 "SB_ON" SOLDER-BRIDGE_R0603-0R 2705.87,1885.84 r270 bottom value="Solder Bridge ON"
SB43 "SB_OFF" SOLDER-BRIDGE_R0603-0R 2705.87,2045.85 r90 bottom value="Solder Bridge OFF"
SB44 "SB_ON" SOLDER-BRIDGE_R0603-0R 3135,1485 r180 bottom value="Solder Bridge ON"
SB45 "SB_OFF" SOLDER-BRIDGE_R0603-0R 2645.87,1885.85 r90 bottom value="Solder Bridge OFF"
SB46 "SB_ON" SOLDER-BRIDGE_R0603-0R 2645.87,2045.84 r270 bottom value="Solder Bridge ON"
SB47 "SB_OFF" SOLDER-BRIDGE_R0603-0R 3309.16,2061.93 r270 bottom value="Solder Bridge OFF"
SB48 "SB_ON" SOLDER-BRIDGE_R0402-0R 2430,860 r90 bottom value="0 ohm"
SB49 "SB_ON" SOLDER-BRIDGE_R0603-0R 2973,2174 r270 bottom value="Solder Bridge ON"
SB50 "SB_ON" SOLDER-BRIDGE_R0603-0R 4103.62,2867 r180 bottom value="Solder Bridge ON"
SB51 "SB_ON" SOLDER-BRIDGE_R0603-0R 4001,2428.38 r90 bottom value="Solder Bridge ON"
SB52 "SB_OFF" SOLDER-BRIDGE_R0603-0R 760.91,934.84 r0 bottom value="Solder Bridge OFF"
SB53 "SB_ON" SOLDER-BRIDGE_R0603-0R 2845,2044.99 r270 bottom value="Solder Bridge ON"
SB54 "SB_ON" SOLDER-BRIDGE_R0603-0R 760.91,989.84 r0 bottom value="Solder Bridge ON"
SB55 "SB_ON" SOLDER-BRIDGE_R0603-0R 3215.32,1290 r180 bottom value="Solder Bridge ON"
SB56 "SB_ON" SOLDER-BRIDGE_R0603-0R 1494.74,1891.22 r180 bottom value="Solder Bridge ON"
SB57 "SB_ON" SOLDER-BRIDGE_R0402-0R 1117.72,1385 r0 bottom value="0 ohm"
SB58 "SB_ON" SOLDER-BRIDGE_R0603-0R 1474.75,2301.22 r0 bottom value="Solder Bridge ON"
SB59 "SB_ON" SOLDER-BRIDGE_R0603-0R 1474.44,2201.22 r0 bottom value="Solder Bridge ON"
SB60 "SB_ON" SOLDER-BRIDGE_R0402-0R 1120,1010 r180 bottom value="0 ohm"
SB61 "SB_ON" SOLDER-BRIDGE_R0603-0R 967.77,2990.91 r0 bottom value="Solder Bridge ON"
SB62 "SB_ON" SOLDER-BRIDGE_R0603-0R 865,1732.62 r90 bottom value="Solder Bridge ON"
SB63 "SB_ON" SOLDER-BRIDGE_R0603-0R 800,1731.24 r90 bottom value="Solder Bridge ON"
SB64 "SB_ON" SOLDER-BRIDGE_R0603-0R 682.76,3045.9 r270 bottom value="Solder Bridge ON"
SB65 "SB_OFF" SOLDER-BRIDGE_R0603-0R 642.76,2360.91 r90 bottom value="Solder Bridge OFF"
SB66 "SB_ON" SOLDER-BRIDGE_R0402-0R 1954,860 r270 top value="0 ohm"
SB67 "SB_ON" SOLDER-BRIDGE_R0402-0R 2911.34,673 r0 bottom value="0 ohm"
SB68 "SB_ON" SOLDER-BRIDGE_R0603-0R 3244.16,2061.93 r270 bottom value="Solder Bridge ON"
SB69 "SB_ON" SOLDER-BRIDGE_R0603-0R 4940,199.99 r270 bottom value="Solder Bridge ON"
SB70 "SB_ON" SOLDER-BRIDGE_R0603-0R 4095,199.99 r270 bottom value="Solder Bridge ON"
SB71 "SB_ON" SOLDER-BRIDGE_R0603-0R 5530,1625 r90 bottom value="Solder Bridge ON"
SB72 "SB_OFF" SOLDER-BRIDGE_R0603-0R 2845,2174.99 r270 bottom value="Solder Bridge OFF"
SB73 "SB_OFF" SOLDER-BRIDGE_R0603-0R 3035,2174 r270 bottom value="Solder Bridge OFF"
SB74 "SB_OFF" SOLDER-BRIDGE_R0603-0R 4103.62,2802 r180 bottom value="Solder Bridge OFF"
SB75 "SB_OFF" SOLDER-BRIDGE_R0603-0R 5667.32,2801 r180 bottom value="Solder Bridge OFF"
SB76 "SB_OFF" SOLDER-BRIDGE_R0603-0R 3886,2841.17 r90 bottom value="Solder Bridge OFF"
SB77 "SB_OFF" SOLDER-BRIDGE_R0603-0R 5668.32,2675 r180 bottom value="Solder Bridge OFF"
SW1 "SW_MECA_1K2" SWI_EAO_09-03290-01_EXTENDED_STRAIGHT_BLACK 220,1110 r90 top value="Mechanical Slide Switch 1K2"
TP1 "Test Point" TP_SMD_1MM 5605,3035 r0 top value="Test Point 1mm"
TP2 "Test Point" TP_SMD_1MM 5610,3130 r0 top value="Test Point 1mm"
TP3 "Test Point" TP_SMD_2MM 5300,1135 r0 bottom
TP4 "Test Point" TP_SMD_1MM 5242.87,2156.22 r90 bottom value="Test Point 1mm"
TP5 "Test Point" TP_SMD_2MM 5253,796 r180 bottom
TP6 "Test Point" TP_SMD_2MM 4781,2710 r270 bottom
TP7 "Test Point" TP_SMD_2MM 4347.83,2689.77 r270 bottom
TP8 "Test Point" TP_SMD_2MM 3975,1680 r180 bottom
TP9 "Test Point" TP_SMD_1MM 2562.52,238.19 r0 bottom value="Test Point 1mm"
TP10 "Test Point" TP_SMD_1MM 2562.52,398.19 r270 bottom value="Test Point 1mm"
TP11 "Test Point" TP_SMD_1MM 421,2921 r90 top value="Test Point 1mm"
TP12 "Test Point" TP_SMD_0-6MM 2454.76,945.91 r0 top
TP13 "Test Point" TP_SMD_0-6MM 2646.76,947.91 r0 top
TP14 "Test Point" TP_SMD_0-6MM 2637.76,1045.91 r0 top
TP15 "Test Point" TP_SMD_0-6MM 2659.76,995.91 r0 top
TP16 "Test Point" TP_SMD_0-6MM 2550.76,947.91 r0 top
TP17 "Test Point" TP_SMD_0-6MM 2716.76,945.91 r0 top
TP18 "Test Point" TP_SMD_0-6MM 2755.76,1045.91 r0 top
TP19 "Test Point" TP_SMD_0-6MM 2765.76,944.91 r0 top
TP20 "Test Point" TP_SMD_0-6MM 2699.76,896.91 r0 top
TP21 "Test Point" TP_SMD_0-6MM 2598.76,947.91 r90 top
TP22 "Test Point" TP_SMD_0-6MM 2589.76,1045.91 r90 top
TP23 "Test Point" TP_SMD_0-6MM 2707.76,1045.91 r90 top
TP24 "Test Point" TP_SMD_0-6MM 2541.76,1045.91 r90 top
TP25 "Test Point" TP_SMD_0-6MM 2502.76,945.91 r90 top
TP26 "Test Point" TP_SMD_0-6MM 2492.76,1045.91 r90 top
TP27 "Test Point" TP_SMD_0-6MM 2851.76,1043.91 r90 top
TP28 "Test Point" TP_SMD_0-6MM 2917.76,907.91 r90 top
TP29 "Test Point" TP_SMD_0-6MM 2803.76,1045.91 r90 top
TP30 "Test Point" TP_SMD_0-6MM 2855.76,944.91 r90 top
TP31 "Test Point" TP_SMD_0-6MM 2811.76,889.91 r90 top
TP32 "Test Point" TP_SMD_0-6MM 2312.76,1415.91 r90 top
TP33 "Test Point" TP_SMD_0-6MM 2372.76,1355.91 r90 top
TP34 "Test Point" TP_SMD_0-6MM 2312.76,1200.91 r90 top
TP35 "Test Point" TP_SMD_0-6MM 2312.76,1250.91 r90 top
TP36 "Test Point" TP_SMD_0-6MM 2377.76,1415.91 r90 top
TP37 "Test Point" TP_SMD_0-6MM 2312.76,1145.91 r90 top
